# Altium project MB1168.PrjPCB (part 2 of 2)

## Sheet Peripherals.SchDoc: Peripherals
size A3; Project: STM32L073Z-EVAL; Date: Not used; ApprovedBy: Not used; CheckedBy: Not used; Author: Not used; CompanyName: STMicroelectronics; DrawnBy: Not used; Engineer: Not used; Organization: Not used; Address1: Not used; Address2: Not used; Address3: Not used; Address4: Not used; DocumentNumber: 5; Revision: Not used; SheetNumber: 6; SheetTotal: 13
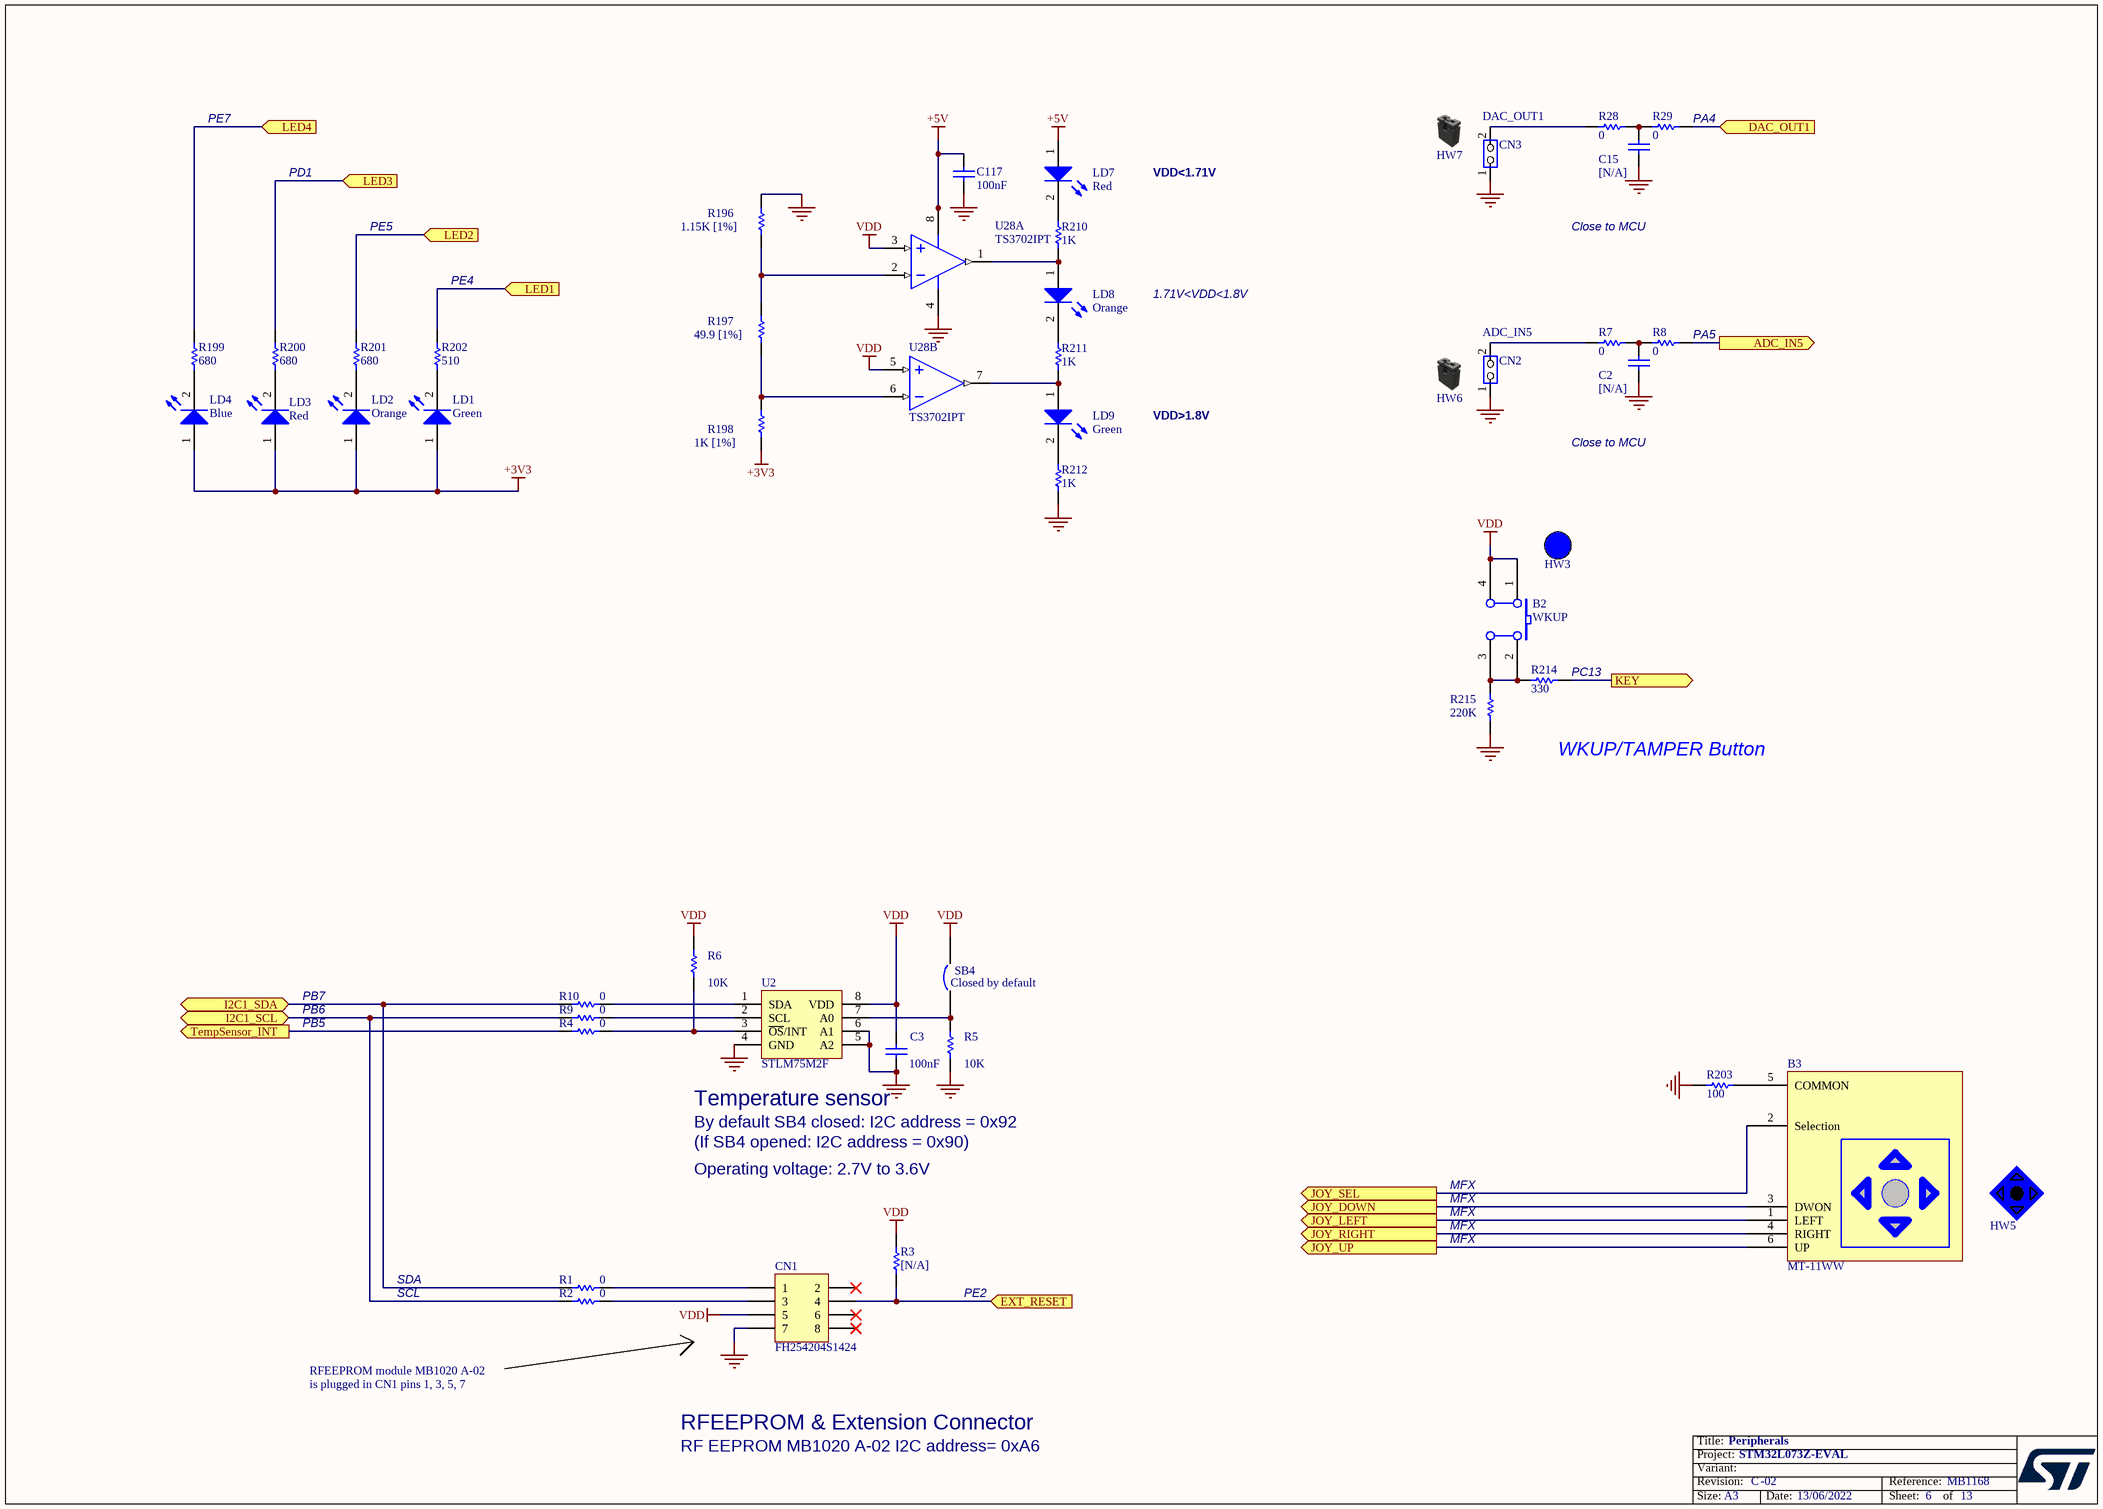
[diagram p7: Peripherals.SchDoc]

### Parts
B2  WKUP  [PB10]
B3  MT-11WW  [MT-008A]
C2  [N/A]  [0603C]
C3  100nF  [0402C]
C15  [N/A]  [0603C]
C117  100nF  [0402C]
CN1  FH254204S1424  [SSM-104-L-DH]
CN2  Silkscreen: ADC_IN5  [SIP2]  (hidden comment: Header 2X1)
CN3  Silkscreen: DAC_OUT1  [SIP2]  (hidden comment: Header 2X1)
HW3  BUTTON_HAT_BLUE  (value not drawn)  (mechanical)
HW5  JOYSTICK_BLUE_HAT  (value not drawn)  (mechanical)
HW6  Shunt Black 2.54mm  (value not drawn)  (mechanical)
HW7  Shunt Black 2.54mm  (value not drawn)  (mechanical)
LD1  Green  [0603D]
LD2  Orange  [0603D]
LD3  Red  [0603D]
LD4  Blue  [0603D]
LD7  Red  [0603D]
LD8  Orange  [0603D]
LD9  Green  [0603D]
R1  0  [0603R]
R2  0  [0603R]
R3  [N/A]  [0603R]
R4  0  [0603R]
R5  10K  [0402R]
R6  10K  [0402R]
R7  0  [0603R]
R8  0  [0603R]
R9  0  [0603R]
R10  0  [0603R]
R28  0  [0603R]
R29  0  [0603R]
R196  1.15K [1%]  [0603R]
R197  49.9 [1%]  [0603R]
R198  1K [1%]  [0603R]
R199  680  [0402R]
R200  680  [0402R]
R201  680  [0402R]
R202  510  [0402R]
R203  100  [0402R]
R210  1K  [0402R]
R211  1K  [0402R]
R212  1K  [0402R]
R214  330  [0603R]
R215  220K  [0402R]
SB4  Closed by default  [SB_0603]
U2  STLM75M2F  [SOIC8_1R27_4R9X6]
U28  TS3702IPT  [TSSOP8_0R65_3X6R4]  (parts A,B of 2)

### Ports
ADC_IN5 (out), DAC_OUT1 (in), EXT_RESET (in), I2C1_SCL (bidir), I2C1_SDA (bidir), JOY_DOWN (out), JOY_LEFT (out), JOY_RIGHT (out), JOY_SEL (out), JOY_UP (out), KEY (out), LED1 (in), LED2 (in), LED3 (in), LED4 (in), TempSensor_INT (out)

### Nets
+3V3: LD1.1(A) LD2.1(A) LD3.1(A) LD4.1(A) R198.1
+5V: C117.2 LD7.1(A) U28.8(V+)
GND: C2.1 C3.1 C15.1 C117.1 CN1.7 CN2.1(COMMON) CN3.1(COMMON) R5.2 R196.2 R203.1 R212.2 R215.2 U2.4(GND) U2.5(A2) U2.6(A1) U28.4(V-)
VDD: B2.1(A0) B2.4(A1) C3.2 CN1.5 R3.2 R6.1 SB4.2 U2.8(VDD) U28.3(IN+) U28.5(IN+)
PA5: R8.2 ; port ADC_IN5
PC13: R214.2 ; port KEY
PD1: R200.1 ; port LED3
PE4: R202.1 ; port LED1
PE5: R201.1 ; port LED2
PE7: R199.1 ; port LED4
NetB2_2: B2.2(B0) B2.3(B1) R214.1 R215.1
NetB3_1: B3.1(LEFT) ; port JOY_LEFT
NetB3_2: B3.2(Selection) ; port JOY_SEL
NetB3_3: B3.3(DWON) ; port JOY_DOWN
NetB3_4: B3.4(RIGHT) ; port JOY_RIGHT
NetB3_5: B3.5(COMMON) R203.2
NetB3_6: B3.6(UP) ; port JOY_UP
NetC2_2: C2.2 R7.2 R8.1
NetC15_2: C15.2 R28.2 R29.1
NetCN1_1: CN1.1 R1.2
NetCN1_3: CN1.3 R2.2
NetCN1_4: CN1.4 R3.1 ; port EXT_RESET
NetCN2_2: CN2.2(NO) R7.1
NetCN3_2: CN3.2(NO) R28.1
NetCN10_14: R4.2 ; port TempSensor_INT
NetJP2_1: R29.2 ; port DAC_OUT1
NetLD1_2: LD1.2(K) R202.2
NetLD2_2: LD2.2(K) R201.2
NetLD3_2: LD3.2(K) R200.2
NetLD4_2: LD4.2(K) R199.2
NetLD7_2: LD7.2(K) R210.1
NetLD8_1: LD8.1(A) R210.2 U28.1(OUT)
NetLD8_2: LD8.2(K) R211.1
NetLD9_1: LD9.1(A) R211.2 U28.7(OUT)
NetLD9_2: LD9.2(K) R212.1
NetR1_1: R1.1 R10.1 ; port I2C1_SDA
NetR2_1: R2.1 R9.1 ; port I2C1_SCL
NetR4_1: R4.1 R6.2 U2.3(~{OS}/INT)
NetR5_1: R5.1 SB4.1 U2.7(A0)
NetR9_2: R9.2 U2.2(SCL)
NetR10_2: R10.2 U2.1(SDA)
NetR196_1: R196.1 R197.2 U28.2(IN-)
NetR197_1: R197.1 R198.2 U28.6(IN-)

Not connected (* = marked no-connect by the designer): CN1 2* 6* 8*

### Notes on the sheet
- PE7
- PD1
- VDD<1.71V
- (near R29) PA4
- PE5
- Close to MCU
- PE4
- 1.71V<VDD<1.8V
- (near R8) PA5
- VDD>1.8V
- (near R214) PC13
- WKUP/TAMPER Button
- PB7
- PB6
- PB5
- Temperature sensor
- By default SB4 closed: I2C address = 0x92
- Operating voltage: 2.7V to 3.6V
- (If SB4 opened: I2C address = 0x90)
- MFX
- SDA
- SCL
- PE2
- RFEEPROM module MB1020 A-02
  is plugged in CN1 pins 1, 3, 5, 7
- RF EEPROM MB1020 A-02 I2C address= 0xA6
- RFEEPROM & Extension Connector

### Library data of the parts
B2 = SW PUSHBUTTON: SE PUSHBUTTON; Ordered by: Subcon; Assembly: Blue; Silkscreen: Wkup/Tamper
B3 = MT-008A: Joystick; Ordered by: Subcon; Assembly: with button
C2 C15 = cap: Capacitor; Value: 100pF; Ordered by: Subcon; Fitted: NO
C3 = cap: Capacitor; Value: 100pF; Ordered by: Subcon
C117 = CAP: Capacitor; Value: 100pF; Ordered by: Subcon
CN1 = SSM-104-L-DH: Header, 5-Pin, Dual row; Manuf_1: towneS; Ordered by: Subcon; Silkscreen: RF_EEPROM; Assembly: with ANT7-M24LR-A (MB1020-A02)
CN2 CN3 = JP2: Manuf_1: LWCONN; Manuf_Part_1: 313102S111116; Ordered by: Subcon
LD1-LD4 LD8 = LED2: Typical RED, GREEN, YELLOW, AMBER GaAs LED; Ordered by: Subcon
LD7 = LED2: Typical RED, GREEN, YELLOW, AMBER GaAs LED; Ordered by: Subcon; Silkscreen: VDD<1.7V
LD9 = LED2: Typical RED, GREEN, YELLOW, AMBER GaAs LED; Ordered by: Subcon; Silkscreen: VDD>1.8V
R1 R2 R4 R7-R10 R28 R29 R196 R197 R199-R203 R214 = Res1: Resistor; Value: 1K; Ordered by: Subcon
R3 = Res1: Resistor; Value: 1K; Ordered by: Subcon; Fitted: NO
R5 R6 R215 = res1: Resistor; Value: 1K; Ordered by: Subcon
R198 R210-R212 = Res1: Resistor; Ordered by: Subcon
SB4 = Circuit Breaker: Ordered by: Subcon; Comments: Solder bridge
U2 = STLM75DW2F: Ordered by: ST; ECCN_US/EU: EAR99/NEC; Ref St: 9177005
U28 = LM393PT: Ordered by: ST; ECCN_US/EU: EAR99/NEC; Ref St: 9177424

## Sheet Power.SchDoc: Power
size A3; Project: STM32L073Z-EVAL; Date: Not used; ApprovedBy: Not used; CheckedBy: Not used; Author: Not used; CompanyName: STMicroelectronics; DrawnBy: Not used; Engineer: Not used; Organization: Not used; Address1: Not used; Address2: Not used; Address3: Not used; Address4: Not used; DocumentNumber: 4; Revision: Not used; SheetNumber: 5; SheetTotal: 13
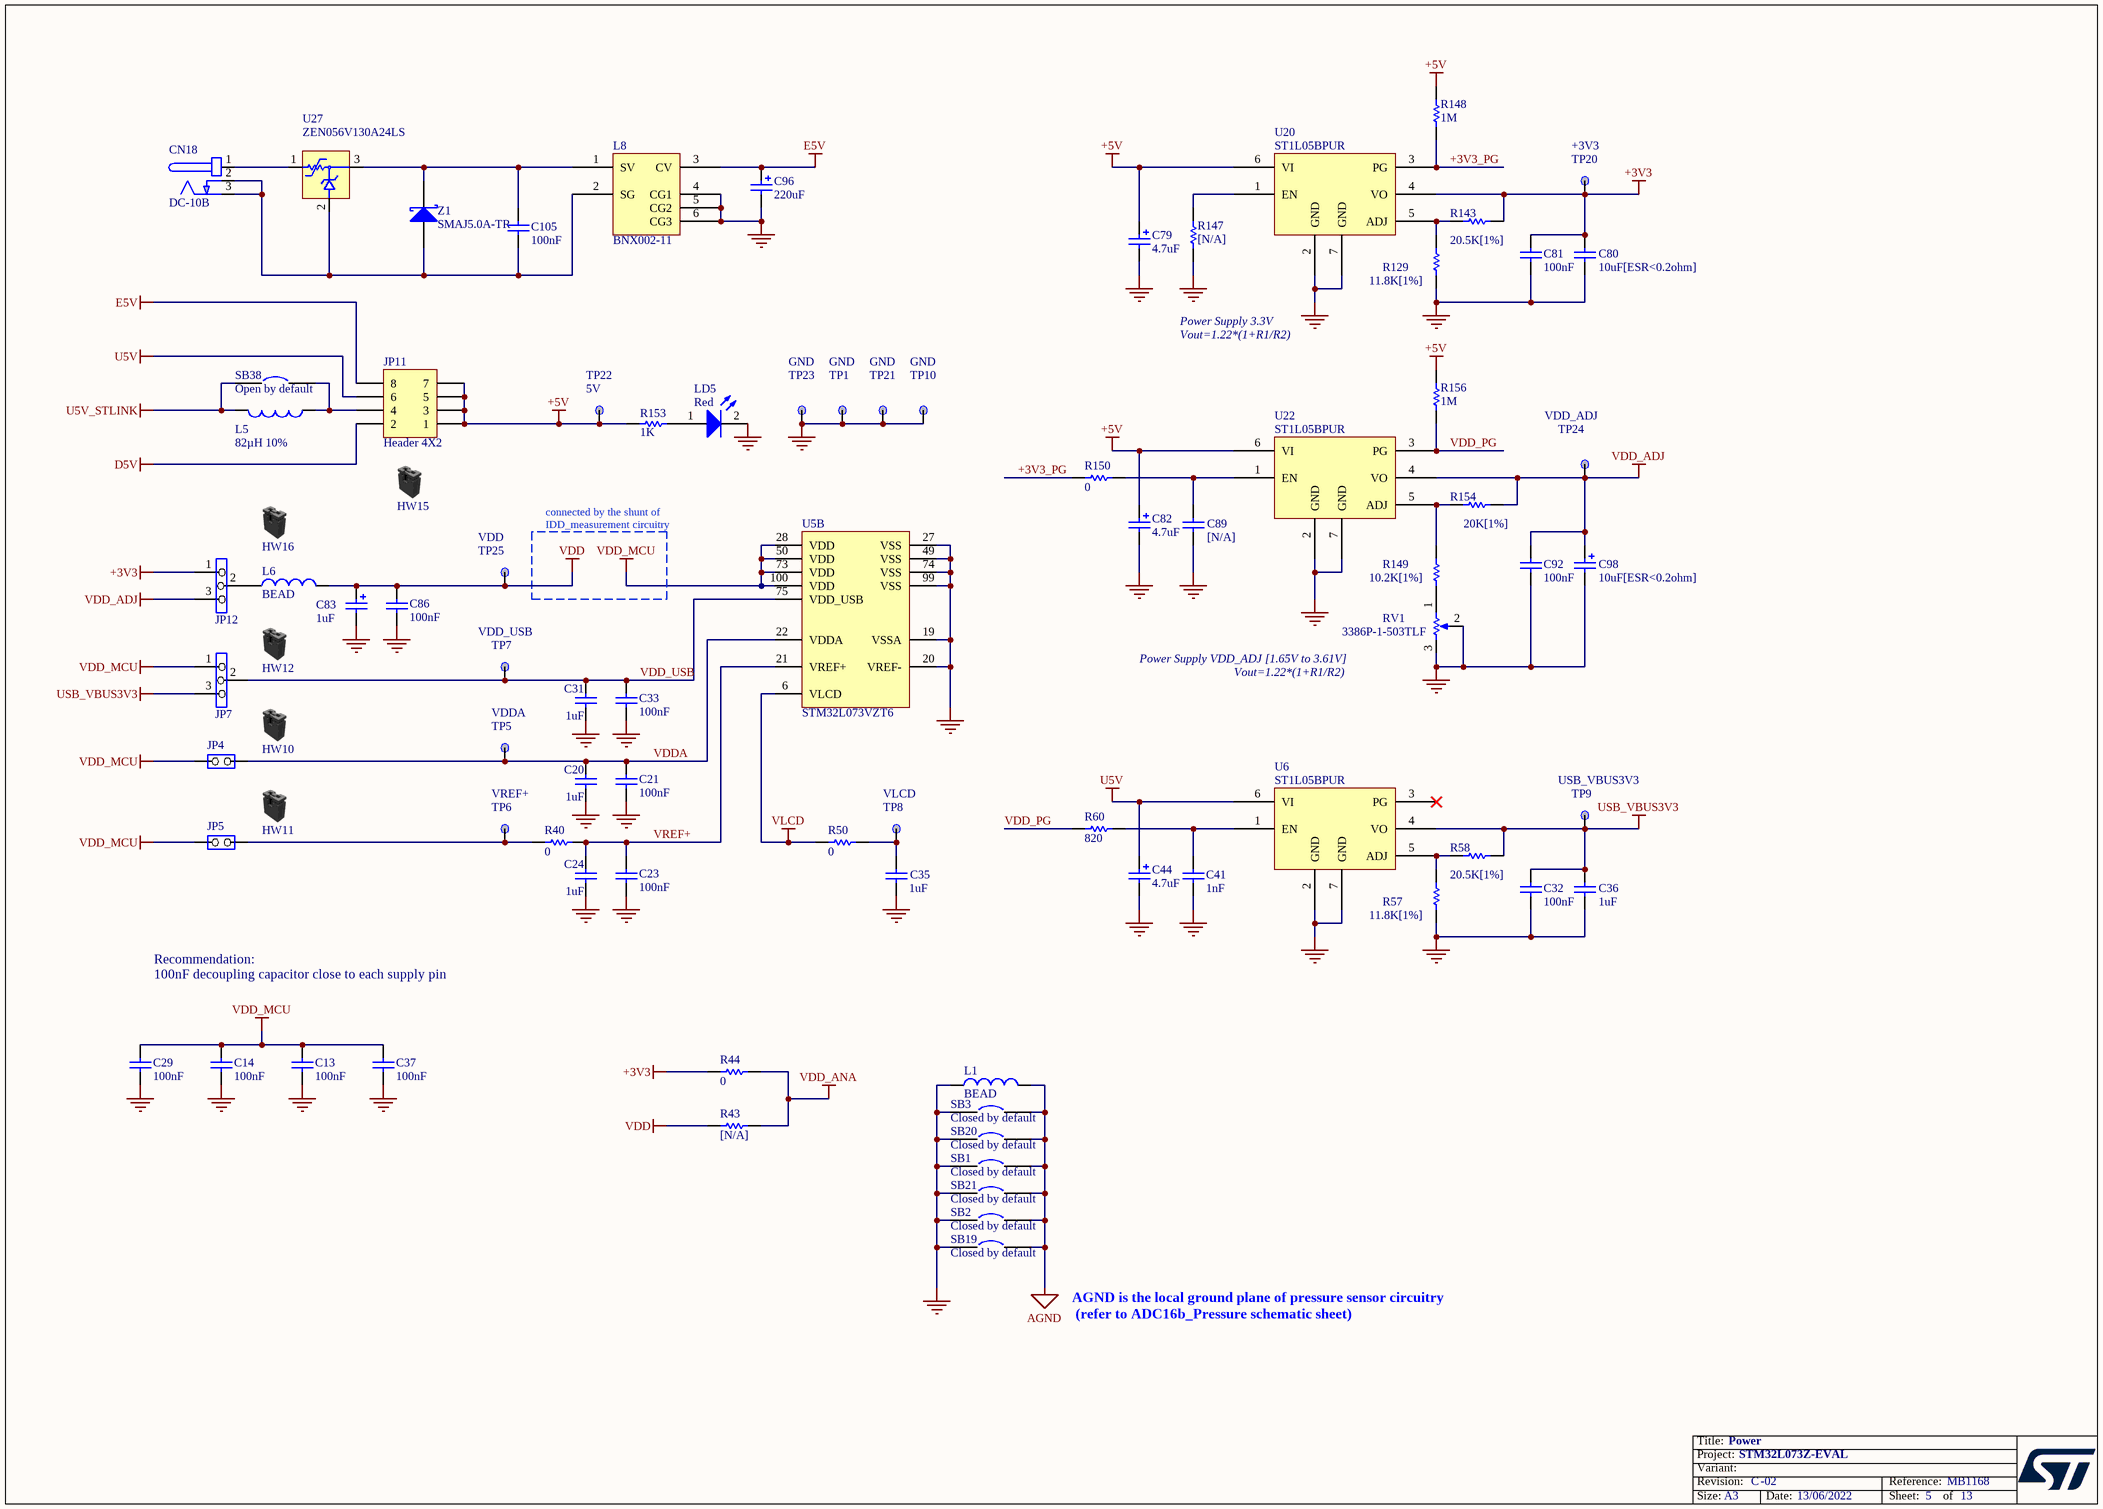
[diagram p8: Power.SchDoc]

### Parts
C13  100nF  [0402C]
C14  100nF  [0402C]
C20  1uF  [0603C]
C21  100nF  [0402C]
C23  100nF  [0402C]
C24  1uF  [0603C]
C29  100nF  [0402C]
C31  1uF  [0603C]
C32  100nF  [0402C]
C33  100nF  [0402C]
C35  1uF  [0603C]
C36  1uF  [0603C]
C37  100nF  [0402C]
C41  1nF  [0603C]
C44  4.7uF  [TAN-A]
C79  4.7uF  [TAN-A]
C80  10uF[ESR<0.2ohm]  [0805C]
C81  100nF  [0402C]
C82  4.7uF  [TAN-A]
C83  1uF  [TAN-A]
C86  100nF  [0402C]
C89  [N/A]  [0603C]
C92  100nF  [0402C]
C96  220uF  [c310m-6]
C98  10uF[ESR<0.2ohm]  [0805C]
C105  100nF  [0402C]
CN18  DC-10B  [PWR_JACK_DC10]
HW10  Shunt Black 2.54mm  (value not drawn)  (mechanical)
HW11  Shunt Black 2.54mm  (value not drawn)  (mechanical)
HW12  Shunt Black 2.54mm  (value not drawn)  (mechanical)
HW15  Shunt Black 2.54mm  (value not drawn)  (mechanical)
HW16  Shunt Black 2.54mm  (value not drawn)  (mechanical)
JP4  (no value)  [SIP2]
JP5  (no value)  [SIP2]
JP7  (no value)  [SIP3]
JP11  Header 4X2  [HDR_2X4_2R54]
JP12  (no value)  [SIP3]
L1  BEAD  [0603L]
L5  82µH 10%  [LSM2_4R9X4R9_H4R1]
L6  BEAD  [0603L]
L8  BNX002-11  [BNX001]
LD5  Red  [0603D]
R40  0  [0603R]
R43  [N/A]  [0603R]
R44  0  [0603R]
R50  0  [0603R]
R57  11.8K[1%]  [0603R]
R58  20.5K[1%]  [0603R]
R60  820  [0603R]
R129  11.8K[1%]  [0603R]
R143  20.5K[1%]  [0603R]
R147  [N/A]  [0603R]
R148  1M  [0603R]
R149  10.2K[1%]  [0603R]
R150  0  [0603R]
R153  1K  [0402R]
R154  20K[1%]  [0603R]
R156  1M  [0603R]
RV1  3386P-1-503TLF  [3386P]
SB1  Closed by default  [SB_0603]
SB2  Closed by default  [SB_0603]
SB3  Closed by default  [SB_0603]
SB19  Closed by default  [SB_0603]
SB20  Closed by default  [SB_0603]
SB21  Closed by default  [SB_0603]
SB38  Open by default  [SB_0603]
TP1  Silkscreen: GND  [TP]  (hidden comment: TP)
TP5  Silkscreen: VDDA  [TP]  (hidden comment: TP)
TP6  Silkscreen: VREF+  [TP]  (hidden comment: TP)
TP7  Silkscreen: VDD_USB  [TP]  (hidden comment: TP)
TP8  Silkscreen: VLCD  [TP]  (hidden comment: TP)
TP9  Silkscreen: USB_VBUS3V3  [TP]  (hidden comment: TP)
TP10  Silkscreen: GND  [TP]  (hidden comment: TP)
TP20  Silkscreen: +3V3  [TP]  (hidden comment: TP)
TP21  Silkscreen: GND  [TP]  (hidden comment: TP)
TP22  Silkscreen: 5V  [TP]  (hidden comment: TP)
TP23  Silkscreen: GND  [TP]  (hidden comment: TP)
TP24  Silkscreen: VDD_ADJ  [TP]  (hidden comment: TP)
TP25  Silkscreen: VDD  [TP]  (hidden comment: TP)
U5  STM32L073VZT6  [IC149_100_025_B5]  (part B of 2)
U6  ST1L05BPUR  [DFN6_0R95_3X3]
U20  ST1L05BPUR  [DFN6_0R95_3X3]
U22  ST1L05BPUR  [DFN6_0R95_3X3]
U27  ZEN056V130A24LS  [TYCO_ZEN056V130A24LS]
Z1  SMAJ5.0A-TR  [sma]

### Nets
+3V3: C80.1 C81.1 JP12.1 R44.1 R143.1 TP20.1 U20.4(VO)
+5V: C79.1 C82.1 JP11.1 JP11.3 JP11.5 JP11.7 R148.1 R153.2 R156.1 TP22.1 U20.6(VI) U22.6(VI)
AGND: L1.2 SB1.2 SB2.2 SB3.2 SB19.2 SB20.2 SB21.2
D5V: JP11.2
E5V: C96.1 JP11.8 L8.3(CV)
GND: C13.1 C14.1 C20.2 C21.1 C23.1 C24.2 C29.1 C31.2 C32.2 C33.1 C35.1 C36.2 C37.1 C41.2 C44.2 C79.2 C80.2 C81.2 C82.2 C83.2 C86.1 C89.1 C92.2 C96.2 C98.2 L1.1 L8.4(CG1) L8.5(CG2) L8.6(CG3) LD5.2(K) R57.2 R129.2 R147.2 RV1.2(TAP) RV1.3(TOP) SB1.1 SB2.1 SB3.1 SB19.1 SB20.1 SB21.1 TP1.1 TP10.1 TP21.1 TP23.1 U5.19(VSSA) U5.20(VREF-) U5.27(VSS) U5.49(VSS) U5.74(VSS) U5.99(VSS) U6.2(GND) U6.7(GND) U20.2(GND) U20.7(GND) U22.2(GND) U22.7(GND)
U5V: C44.1 JP11.6 U6.6(VI)
U5V_STLINK: L5.2 SB38.1
USB_VBUS3V3: C32.1 C36.1 JP7.3 R58.1 TP9.1 U6.4(VO)
VDD: C83.1 C86.2 L6.2 R43.1 TP25.1
VDD_ADJ: C92.1 C98.1 JP12.3 R154.1 TP24.1 U22.4(VO)
VDD_ANA: R43.2 R44.2
VDD_MCU: C13.2 C14.2 C29.2 C37.2 JP4.1(COMMON) JP5.1(COMMON) JP7.1 U5.28(VDD) U5.50(VDD) U5.73(VDD) U5.100(VDD)
VLCD: R50.1 U5.6(VLCD)
+3V3_PG: R148.2 R150.1 U20.3(PG)
VDD_PG: R60.1 R156.2 U22.3(PG)
VDD_USB: C31.1 C33.2 JP7.2 TP7.1 U5.75(VDD_USB)
VDDA: C20.1 C21.2 JP4.2(NO) TP5.1 U5.22(VDDA)
VREF+: C23.2 C24.1 R40.2 U5.21(VREF+)
NetC35_2: C35.2 R50.2 TP8.1
NetC41_1: C41.1 R60.2 U6.1(EN)
NetC89_2: C89.2 R150.2 U22.1(EN)
NetC105_1: C105.1 L8.1(SV) U27.3 Z1.2(K)
NetC105_2: C105.2 CN18.2(GND) CN18.3(GND) L8.2(SG) U27.2 Z1.1(A)
NetCN18_1: CN18.1(+) U27.1
NetJP5_2: JP5.2(NO) R40.1 TP6.1
NetJP11_4: JP11.4 L5.1 SB38.2
NetJP12_2: JP12.2 L6.1
NetLD5_1: LD5.1(A) R153.1
NetR57_1: R57.1 R58.2 U6.5(ADJ)
NetR129_1: R129.1 R143.2 U20.5(ADJ)
NetR147_1: R147.1 U20.1(EN)
NetR149_1: R149.1 R154.2 U22.5(ADJ)
NetR149_2: R149.2 RV1.1(BOT)

Not connected (* = marked no-connect by the designer): U6 3(PG)*

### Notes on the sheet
- Power Supply 3.3V
- Vout=1.22*(1+R1/R2)
- (near TP25) connected by the shunt of
  IDD_measurement circuitry
- Power Supply VDD_ADJ [1.65V to 3.61V]
- Recommendation:
  100nF decoupling capacitor close to each supply pin
- AGND is the local ground plane of pressure sensor circuitry
  (refer to ADC16b_Pressure schematic sheet)

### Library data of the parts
C13 C14 C29 C37 = CAP: Capacitor; Ordered by: Subcon
C20 C24 C31 C35 = CAP: Capacitor; Value: 100nF; Ordered by: Subcon
C21 C23 C32 C33 C36 C41 C81 C86 C92 = Cap: Capacitor; Value: 10nF; Ordered by: Subcon
C44 = Cap Pol1: Polarized Capacitor (Radial); Value: 100pF; Ordered by: Subcon
C79 C82 C96 = Cap Pol1: Polarized Capacitor (Radial); Ordered by: Subcon
C80 = Cap: Capacitor; Value: 10uF; Ordered by: Subcon
C83 = Cap Pol1: Polarized Capacitor; Ordered by: Subcon
C89 = cap: as C2 on sheet Peripherals
C98 = Cap Pol1: Polarized Capacitor (Radial); Value: 10uF; Ordered by: Subcon
C105 = CAP: as C117 on sheet Peripherals
CN18 = PJ202A: Manuf_1: wealthmetal; Manuf_Part_1: DC-005-2.5; Ordered by: Subcon; Comments: power jack; Silkscreen: PSU_E5V
JP4 = JP2: Ordered by: Subcon; Silkscreen: VDDA; Assembly: closed
JP5 = JP2: Ordered by: Subcon; Silkscreen: VREF+; Assembly: closed
JP7 = Jumper3: Ordered by: Subcon; Silkscreen: 1,2: VDD_MCU / 2,3: VBUS; Assembly: 1-2 closed (MCU)
JP11 = Header 4X2: Header, 4-Pin, Dual row; Ordered by: Subcon; Silkscreen: 7,8: E5V /5,6: U5V / 3,4: STlk / 1,2: D5V; Assembly: 7-8 (E5V)
JP12 = Jumper3: Ordered by: Subcon; Silkscreen: 1,2: +3V3 / 2,3: VDD_ADJ; Assembly: 1-2 (+3V3)
L1 L6 = Inductor: Bead,600R,350mA,0603; Manuf_1: Tai-tech; Manuf_Part_1: FCM1608KF-601T05; Manuf_2: Wurth Elektronik; Manuf_Part_2: 742863160; Value: 100uH; Ordered by: Subcon
L5 = Ind_82µH_0.65A_10%: Power Inductor 82µH 0,65A; Manuf_Part_1: PSI054T-820MS-11; Manuf_1: CYNTEC; Manuf_Part_2: A916CY-820M; Manuf_2: TOKO; Order_2: 752-1406; Ordered by: Subcon
L8 = BNX002: Manuf_1: MURATA; Ordered by: Subcon
LD5 = LED2: Typical RED, GREEN, YELLOW, AMBER GaAs LED; Ordered by: Subcon; Silkscreen: +5V
R40 R44 R50 R57 R58 R129 R143 R149 R154 = Res1: Resistor; Value: 1K; Ordered by: Subcon
R43 R147 = res1: Resistor; Value: 1K; Ordered by: Subcon; Fitted: NO
R60 R148 R150 R156 = res1: Resistor; Value: 1K; Ordered by: Subcon
R153 = res1: Resistor; Ordered by: Subcon
RV1 = RV: Potentiometer 50K; Ordered by: Subcon; Comments: 50K potentiometer; Silkscreen: VDD_ADJ
SB1-SB3 SB19-SB21 = Circuit Breaker: as SB4 on sheet Peripherals
SB38 = Circuit Breaker: Ordered by: Subcon; Comments: Solder bridge; Fitted: NO
TP1 TP5-TP10 TP20-TP25 = TP: Ordered by: Subcon; Fitted: NO
U5 = BigNemo: Manuf_Part_1: FG=32L073VZT6$x3 cut 2.0 marking "B"; Ordered by: ST; ECCN_US/EU: 3A991A2/NEC; Ref St: 9175165
U6 U20 U22 = ST1L05: Ordered by: ST; ECCN_US/EU: EAR99/NEC; Ref St: 9176239
U27 = ZEN056V130A24LS: Ordered by: Subcon; ECCN_US/EU: EAR99/NEC
Z1 = D Schottky: Schottky Diode; Code - JEDEC: DO-214-AA; Ordered by: Subcon; ECCN_US/EU: EAR99/NEC

## Sheet STLINK.SchDoc: STLINK
size A3; Project: STM32L073Z-EVAL; Date: Not used; ApprovedBy: Not used; CheckedBy: Not used; Author: Not used; CompanyName: STMicroelectronics; DrawnBy: Not used; Engineer: Not used; Organization: Not used; Address1: Not used; Address2: Not used; Address3: Not used; Address4: Not used; DocumentNumber: 12; Revision: Not used; SheetNumber: 13; SheetTotal: 13
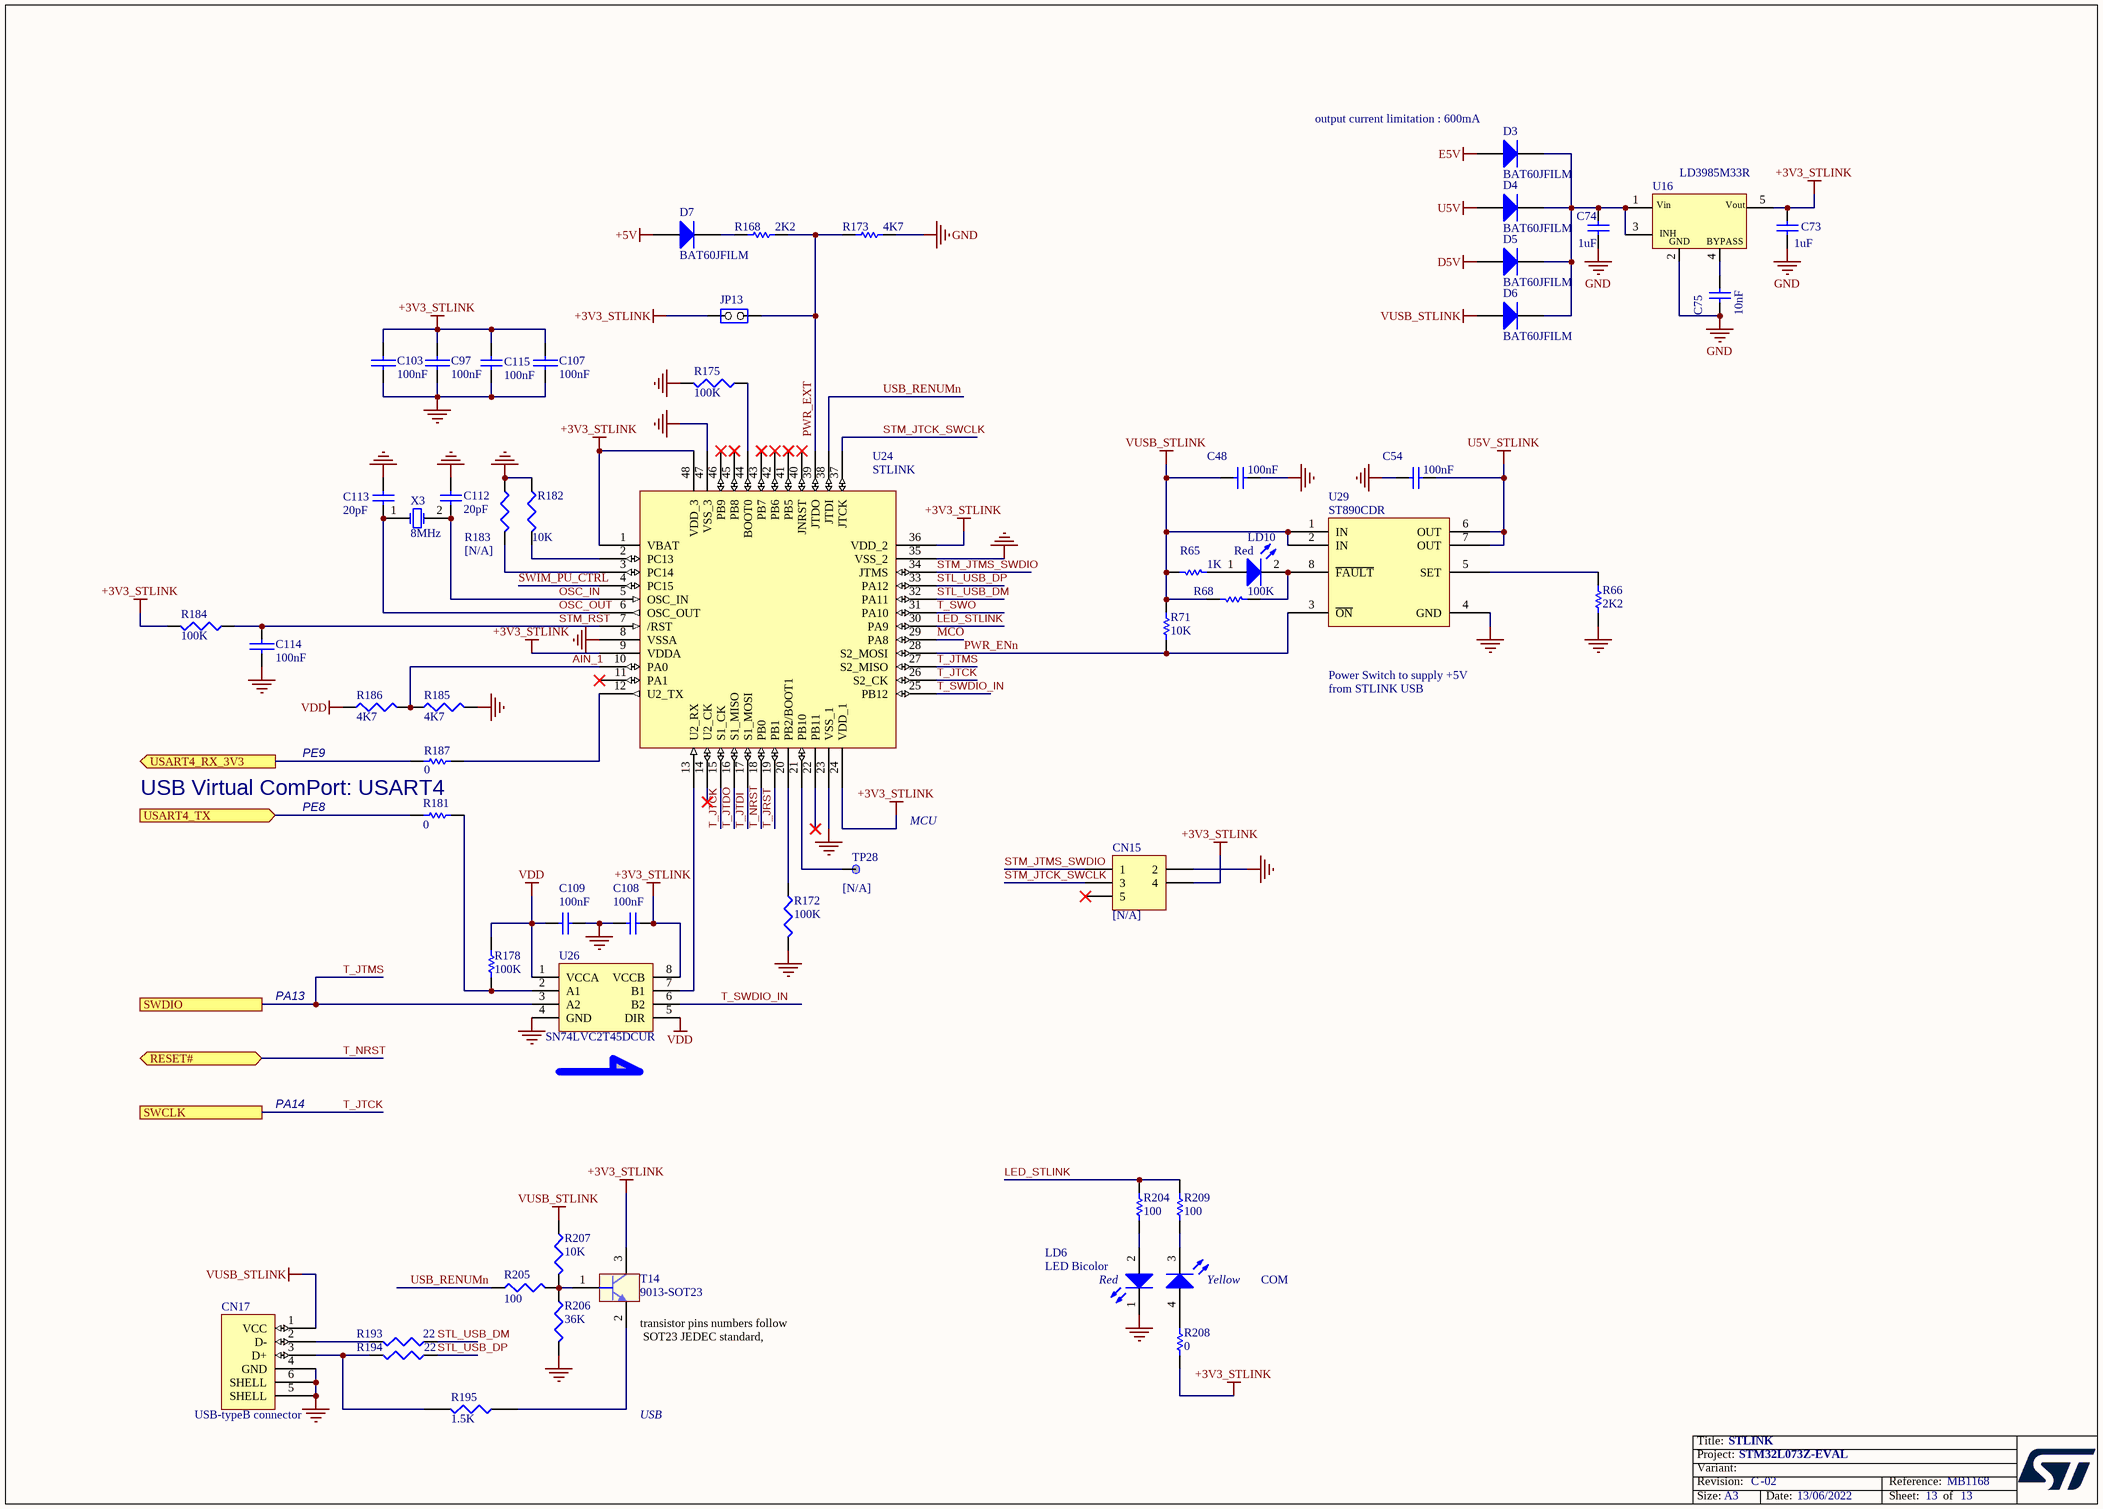
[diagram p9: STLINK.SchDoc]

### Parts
C48  100nF  [0402C]
C54  100nF  [0402C]
C73  1uF  [0603C]
C74  1uF  [0603C]
C75  10nF  [0402C]
C97  100nF  [0402C]
C103  100nF  [0402C]
C107  100nF  [0402C]
C108  100nF  [0402C]
C109  100nF  [0402C]
C112  20pF  [0402C]
C113  20pF  [0402C]
C114  100nF  [0402C]
C115  100nF  [0402C]
CN15  [N/A]  [HDR_2X3-1_2R54-6]
CN17  USB-typeB connector  [USB-B]
D3  BAT60JFILM  [SOD-323]
D4  BAT60JFILM  [SOD-323]
D5  BAT60JFILM  [SOD-323]
D6  BAT60JFILM  [SOD-323]
D7  BAT60JFILM  [SOD-323]
JP13  (no value)  [SIP2]
LD6  LED Bicolor  Silkscreen: COM  [LED2_3528]
LD10  Red  [0603D]
R65  1K  [0402R]
R66  2K2  [0402R]
R68  100K  [0402R]
R71  10K  [0402R]
R168  2K2  [0402R]
R172  100K  [0402R]
R173  4K7  [0402R]
R175  100K  [0402R]
R178  100K  [0402R]
R181  0  [0603R]
R182  10K  [0402R]
R183  [N/A]  [0603R]
R184  100K  [0402R]
R185  4K7  [0402R]
R186  4K7  [0402R]
R187  0  [0603R]
R193  22  [0402R]
R194  22  [0402R]
R195  1.5K  [0402R]
R204  100  [0402R]
R205  100  [0402R]
R206  36K  [0402R]
R207  10K  [0402R]
R208  0  [0603R]
R209  100  [0402R]
T14  9013-SOT23  [SOT-23]
TP28  [N/A]  [TP]
U16  LD3985M33R  [SOT23-5]
U24  STLINK  [LQFP48_0R5_9X9]
U26  SN74LVC2T45DCUR  [USOP8_0R5_2X3R1]
U29  ST890CDR  [SOIC8_1R27_4R9X6]
X3  8MHz  [XTAL_2SM_12R7X4R7]

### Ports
RESET# (bidir), SWCLK, SWDIO, USART4_RX_3V3 (out), USART4_TX (in)

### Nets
+3V3_STLINK: C73.1 C97.2 C103.2 C107.2 C108.1 C115.1 CN15.4 JP13.1(COMMON) R184.2 R208.2 T14.3(C) U16.5(Vout) U24.1(VBAT) U24.9(VDDA) U24.24(VDD_1) U24.36(VDD_2) U24.48(VDD_3) U26.8(VCCB)
+5V: D7.1(A)
D5V: D5.1(A)
E5V: D3.1(A)
GND: C48.2 C54.1 C73.2 C74.2 C75.2 C97.1 C103.1 C107.1 C108.2 C109.2 C112.1 C113.1 C114.1 C115.2 CN15.2 CN17.4(GND) CN17.5(SHELL) CN17.6(SHELL) LD6.1(RED_cathode) R66.2 R172.2 R173.1 R175.2 R182.1 R183.1 R185.2 R206.2 U16.2(GND) U24.8(VSSA) U24.23(VSS_1) U24.35(VSS_2) U24.47(VSS_3) U26.4(GND) U29.4(GND)
U5V: D4.1(A)
U5V_STLINK: C54.2 U29.6(OUT) U29.7(OUT)
VDD: C109.1 R178.1 R186.1 U26.1(VCCA) U26.5(DIR)
VUSB_STLINK: C48.1 CN17.1(VCC) D6.1(A) R65.1 R68.1 R71.2 R207.1 U29.1(IN) U29.2(IN)
AIN_1: R185.1 R186.2 U24.10(PA0)
LED_STLINK: R204.1 R209.1 U24.30(PA9)
MCO: U24.29(PA8)
OSC_IN: C112.2 U24.5(OSC_IN) X3.2(OSC2)
OSC_OUT: C113.2 U24.6(OSC_OUT) X3.1(OSC1)
PE8: R181.1 ; port USART4_TX
PE9: R187.2 ; port USART4_RX_3V3
PWR_ENn: R71.1 U24.28(S2_MOSI) U29.3(~{ON})
PWR_EXT: JP13.2(NO) R168.1 R173.2 U24.39(JTDO)
STL_USB_DM: R193.1 U24.32(PA11)
STL_USB_DP: R194.1 U24.33(PA12)
STM_JTCK_SWCLK: CN15.3 U24.37(JTCK)
STM_JTMS_SWDIO: CN15.1 U24.34(JTMS)
STM_RST: C114.2 R184.1 U24.7(/RST)
SWIM_PU_CTRL: U24.4(PC15)
T_JRST: U24.19(PB1)
T_JTCK: U24.15(S1_CK) U24.26(S2_CK) ; port SWCLK
T_JTDI: U24.17(S1_MOSI)
T_JTDO: U24.16(S1_MISO)
T_JTMS: U24.27(S2_MISO) U26.3(A2) ; port SWDIO
T_NRST: U24.18(PB0) ; port RESET#  [project net RESET#]
T_SWDIO_IN: U24.25(PB12) U26.6(B2)
T_SWO: U24.31(PA10)
USB_RENUMn: R205.1 U24.38(JTDI)
NetC74_1: C74.1 D3.2(K) D4.2(K) D5.2(K) D6.2(K) U16.1(Vin) U16.3(CE)
NetC75_1: C75.1 U16.4(BYPASS)
NetCN17_2: CN17.2(D-) R193.2
NetCN17_3: CN17.3(D+) R194.2 R195.2
NetD7_2: D7.2(K) R168.2
NetLD6_2: LD6.2(Red_anode) R204.2
NetLD6_3: LD6.3(YellowGreen_cathode) R209.2
NetLD6_4: LD6.4(YellowGreen_anode) R208.1
NetLD10_1: LD10.1(A) R65.2
NetLD10_2: LD10.2(K) R68.2 U29.8(~{FAULT})
NetR66_1: R66.1 U29.5(SET)
NetR172_1: R172.1 U24.20(PB2/BOOT1)
NetR175_1: R175.1 U24.44(BOOT0)
NetR178_2: R178.2 R181.2 U26.2(A1)
NetR182_2: R182.2 U24.2(PC13)
NetR183_2: R183.2 U24.3(PC14)
NetR187_1: R187.1 U24.12(U2_TX)
NetR195_1: R195.1 T14.2(E)
NetR205_2: R205.2 R206.1 R207.2 T14.1(B)
NetTP28_1: TP28.1 U24.21(PB10)
NetU24_13: U24.13(U2_RX) U26.7(B1)

Not connected (* = marked no-connect by the designer): CN15 5*; U24 11(PA1)* 14(U2_CK)* 22(PB11)* 40(JNRST)* 41(PB5)* 42(PB6)* 43(PB7)* 45(PB8)* 46(PB9)*

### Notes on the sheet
- (near D3) output current limitation : 600mA
- Power Switch to supply +5V from STLINK USB
- PE9
- USB Virtual ComPort: USART4
- PE8
- MCU
- PA13
- PA14
- (near T14) transistor pins numbers follow
  SOT23 JEDEC standard,
- USB

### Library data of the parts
C48 C54 = Capacitor_ST: Capacitor 0402 / 0603 / 0805; Ordered by: Subcon
C73 C74 = CAP: as C20 on sheet Power
C75 = Cap: Capacitor; Ordered by: Subcon
C97 C103 C107 C114 = CAP: Ordered by: Subcon
C108 C109 C112 C113 = CAP: as C117 on sheet Peripherals
C115 = Cap: as C21 on sheet Power
CN15 = Header 3X2: Header, 3-Pin, Dual row; Ordered by: Subcon; Fitted: NO
CN17 = USB-typeB connector: Manuf_1: txgagroup; Manuf_Part_1: 4414BF20BO; Ordered by: Subcon; Silkscreen: ST-LINK/V2
D3-D7 = Diode: Default Diode; Code - JEDEC: DO-214-AB; Ordered by: ST; ECCN_US/EU: EAR99/NEC; Ref St: 9151097
JP13 = JP2: Ordered by: Subcon; Silkscreen: Pwr_ext; Assembly: opened
LD6 = HSMF-A201-A00J1: Ordered by: Subcon
LD10 = LED2: as LD1 on sheet Peripherals
R65 = Res1: Resistor; Ordered by: Subcon
R66 R168 R173 = res1: Resistor; Value: 1K; Ordered by: Subcon
R68 R178 R181 R187 R204 R208 R209 = Res1: Resistor; Value: 1K; Ordered by: Subcon
R71 = Resistor_ST: Resistor; Ordered by: Subcon
R172 R175 R184 R193 R194 = RES1: Resistor; Ordered by: Subcon
R182 R205-R207 = R: Resistor; Right: 20; Bottom: 30; Ordered by: Subcon
R183 = R: Right: 20; Bottom: 30; Ordered by: Subcon; Fitted: NO
R185 R186 R195 = RES1: Ordered by: Subcon
T14 = 9013-SOT23: NPN Bipolar Transistor; Manuf_Part_1: MMBT2222ALT1G; Ordered by: Subcon; ECCN_US/EU: EAR99/NEC
TP28 = TP: Ordered by: Subcon; Fitted: NO
U16 = LD3985M33R: Ultra low drop-low noise BiCMOS voltage, regulators low ESR capacitors compatible; Manuf_1: ST; Ref St: 9176161; ECCN_US/EU: EAR99/NEC
U24 = STM32F10x(48pin): Manuf_Part_1: STM32F103CBT6; Ordered by: ST; ECCN_US/EU: 3A991A2/NEC; Ref St: 9175111
U26 = SN74LVC2T45DCUT: Ordered by: Subcon; ECCN_US/EU: EAR99/NEC
U29 = ST890CDR: Ordered by: ST; ECCN_US/EU: EAR99/NEC; Ref St: 9172002
X3 = XTAL: Crystal Oscillator; Ordered by: Subcon

## Sheet TFT_MicroSD.SchDoc: TFT_MicroSD
size A3; Project: STM32L073Z-EVAL; Date: Not used; ApprovedBy: Not used; CheckedBy: Not used; Author: Not used; CompanyName: STMicroelectronics; DrawnBy: Not used; Engineer: Not used; Organization: Not used; Address1: Not used; Address2: Not used; Address3: Not used; Address4: Not used; DocumentNumber: 6; Revision: Not used; SheetNumber: 7; SheetTotal: 13
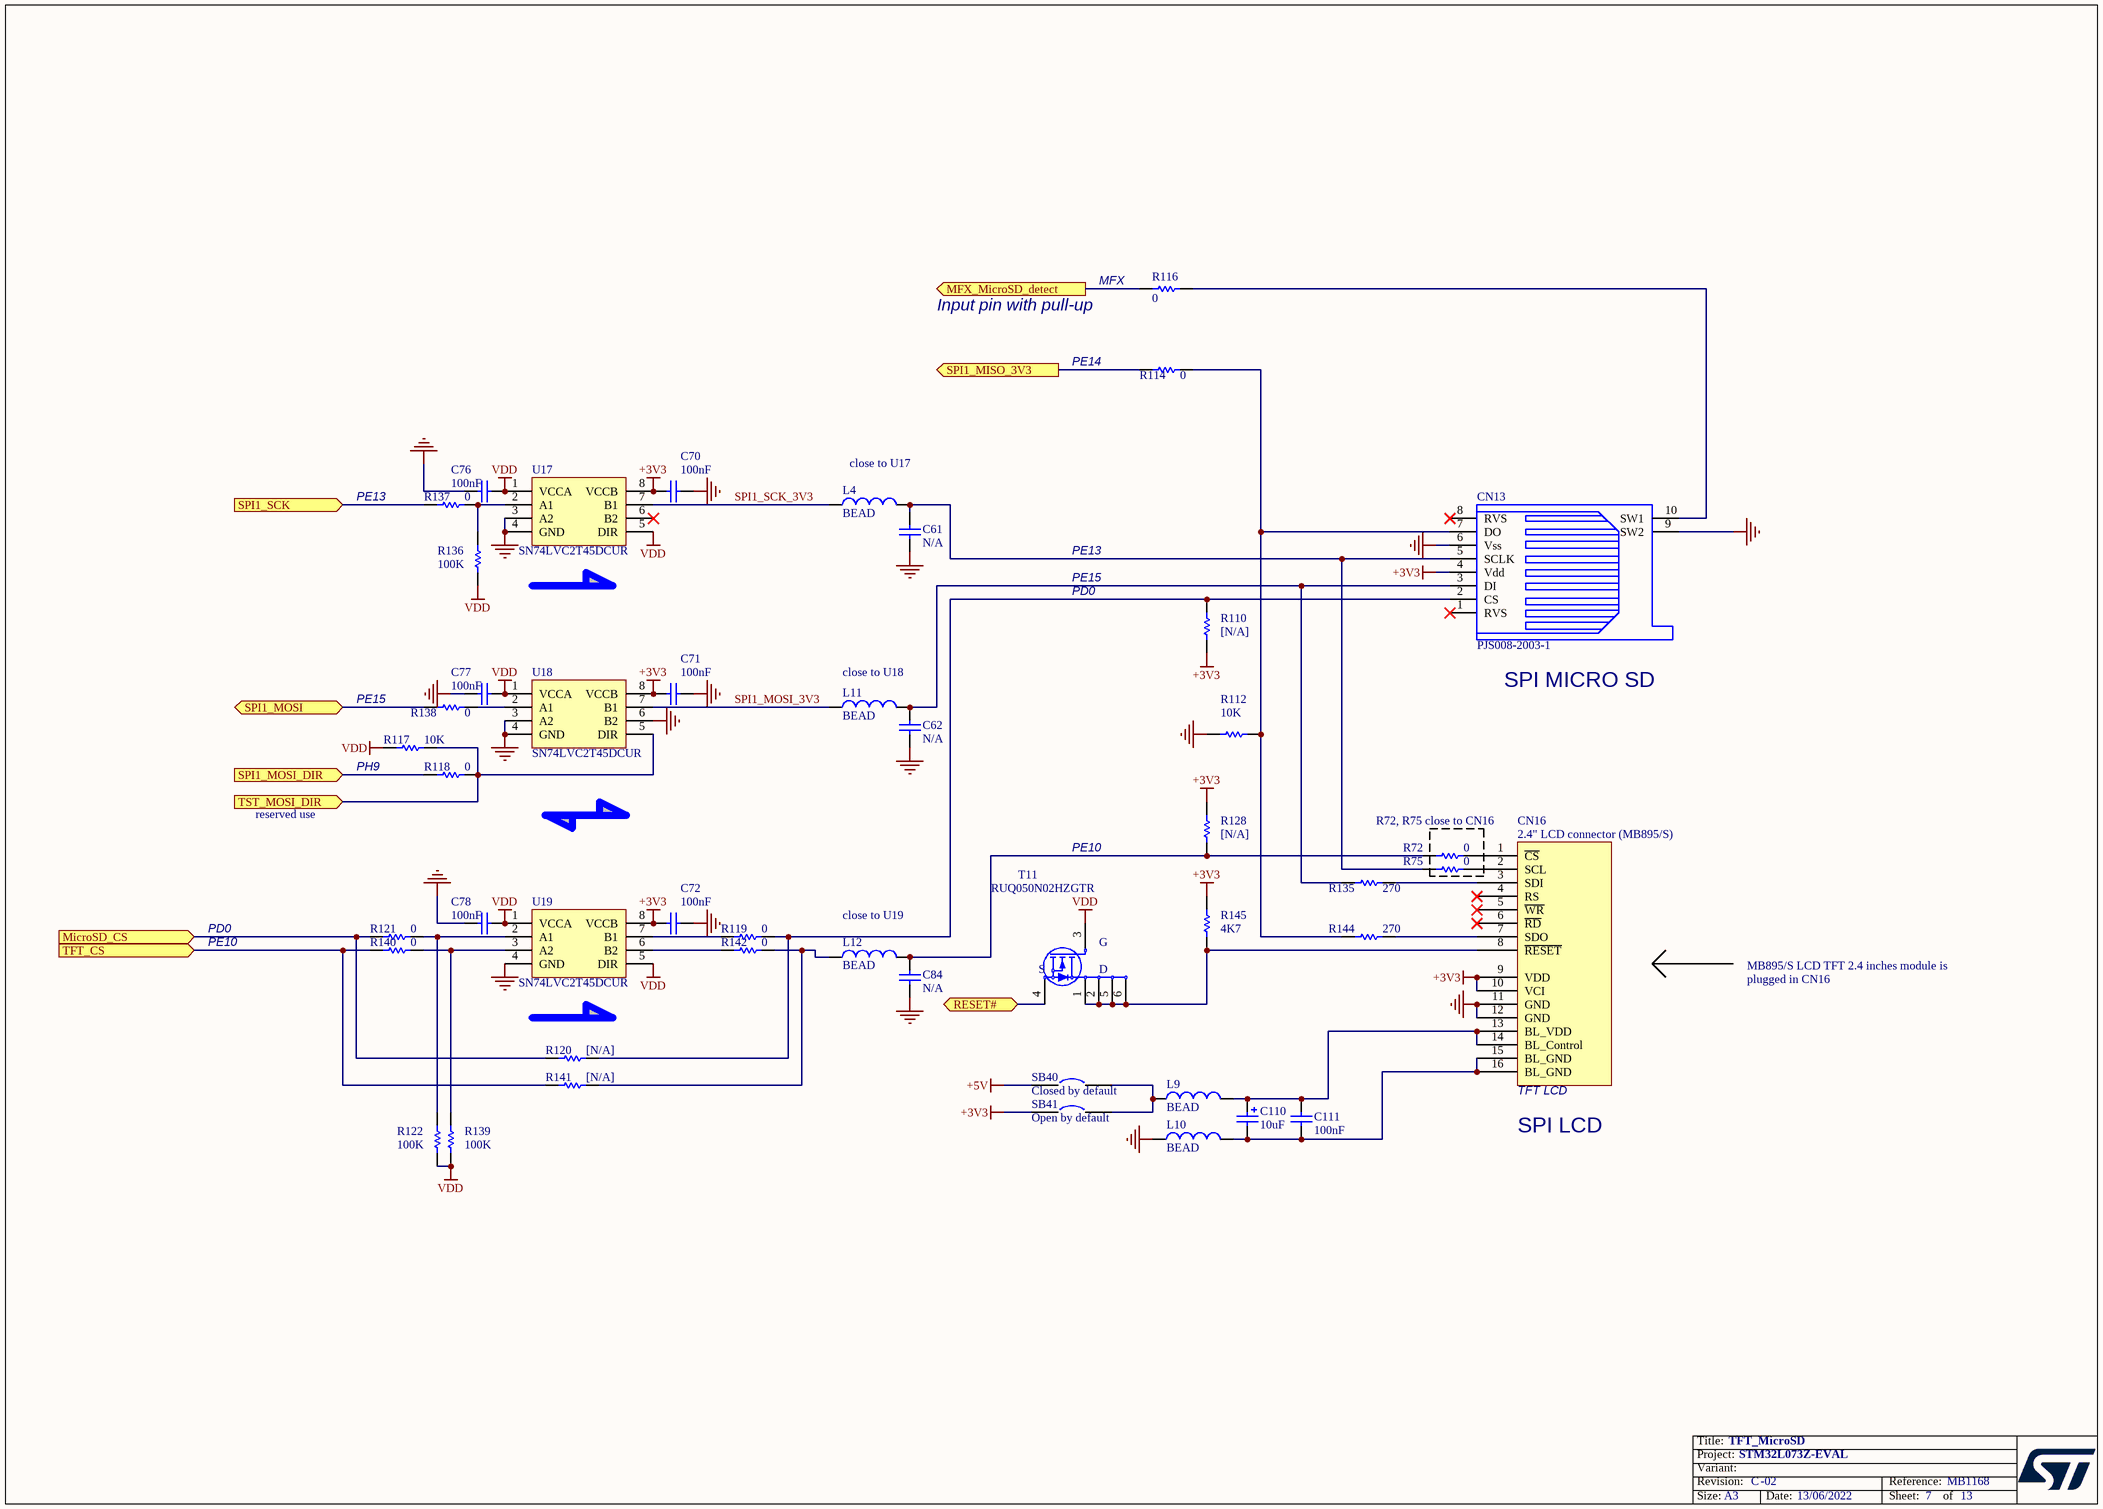
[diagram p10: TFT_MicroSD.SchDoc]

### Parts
C61  N/A  [0603C]
C62  N/A  [0603C]
C70  100nF  [0402C]
C71  100nF  [0402C]
C72  100nF  [0402C]
C76  100nF  [0402C]
C77  100nF  [0402C]
C78  100nF  [0402C]
C84  N/A  [0603C]
C110  10uF  [TAN-A]
C111  100nF  [0402C]
CN13  PJS008-2003-1  [MSD_PJS008_]
CN16  2.4" LCD connector (MB895/S)  [MB895CS]
L4  BEAD  [0603L]
L9  BEAD  [0603L]
L10  BEAD  [0603L]
L11  BEAD  [0603L]
L12  BEAD  [0603L]
R72  0  [0603R]
R75  0  [0603R]
R110  [N/A]  [0603R]
R112  10K  [0402R]
R114  0  [0603R]
R116  0  [0603R]
R117  10K  [0402R]
R118  0  [0603R]
R119  0  [0603R]
R120  [N/A]  [0603R]
R121  0  [0603R]
R122  100K  [0603R]
R128  [N/A]  [0603R]
R135  270  [0603R]
R136  100K  [0603R]
R137  0  [0603R]
R138  0  [0603R]
R139  100K  [0603R]
R140  0  [0603R]
R141  [N/A]  [0603R]
R142  0  [0603R]
R144  270  [0603R]
R145  4K7  [0402R]
SB40  Closed by default  [SB_0603]
SB41  Open by default  [SB_0603]
T11  RUQ050N02HZGTR  [SOT23-6L]
U17  SN74LVC2T45DCUR  [USOP8_0R5_2X3R1]
U18  SN74LVC2T45DCUR  [USOP8_0R5_2X3R1]
U19  SN74LVC2T45DCUR  [USOP8_0R5_2X3R1]

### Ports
MFX_MicroSD_detect (out), MicroSD_CS (in), RESET# (bidir), SPI1_MISO_3V3 (out), SPI1_MOSI (bidir), SPI1_MOSI_DIR (in), SPI1_SCK (in), TFT_CS (in), TST_MOSI_DIR (in)

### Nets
+3V3: C70.2 C71.2 C72.2 CN13.4(Vdd) CN16.9(VDD) CN16.10(VCI) R110.2 R128.2 R145.2 SB41.1 U17.8(VCCB) U18.8(VCCB) U19.8(VCCB)
+5V: SB40.1
GND: C61.1 C62.1 C70.1 C71.1 C72.1 C76.1 C77.1 C78.1 C84.1 CN13.6(Vss) CN13.9(SW2) CN16.11(GND) CN16.12(GND) L10.1 R112.1 U17.3(A2) U17.4(GND) U18.3(A2) U18.4(GND) U18.6(B2) U19.4(GND)
VDD: C76.2 C77.2 C78.2 R117.2 R122.2 R136.2 R139.2 T11.3(G) U17.1(VCCA) U17.5(DIR) U18.1(VCCA) U19.1(VCCA) U19.5(DIR)
PD0: R120.1 R121.2 ; port MicroSD_CS
PE10: R140.1 R141.1 ; port TFT_CS
PE13: R137.2 ; port SPI1_SCK
PE14: R114.2 ; port SPI1_MISO_3V3
PE15: R138.2 ; port SPI1_MOSI
PH9: R118.2 ; port SPI1_MOSI_DIR
RESET#: T11.4(S) ; port RESET#
SPI1_MOSI_3V3: L11.1 U18.7(B1)
SPI1_SCK_3V3: L4.1 U17.7(B1)
NetC61_2: C61.2 CN13.5(SCLK) L4.2 R75.1
NetC62_2: C62.2 CN13.3(DI) L11.2 R135.2
NetC84_2: C84.2 L12.2 R72.1 R128.1
NetC110_1: C110.1 C111.1 CN16.13(BL_VDD) CN16.14(BL_Control) L9.2
NetC110_2: C110.2 C111.2 CN16.15(BL_GND) CN16.16(BL_GND) L10.2
NetCN13_2: CN13.2(CS) R110.1 R119.1 R120.2
NetCN13_7: CN13.7(DO) R112.2 R114.1 R144.1
NetCN13_10: CN13.10(SW1) R116.2
NetCN16_1: CN16.1(~{CS}) R72.2
NetCN16_2: CN16.2(SCL) R75.2
NetCN16_3: CN16.3(SDI) R135.1
NetCN16_7: CN16.7(SDO) R144.2
NetCN16_8: CN16.8(~{RESET}) R145.1 T11.1(S) T11.2(S) T11.5(D) T11.6(D)
NetL9_1: L9.1 SB40.2 SB41.2
NetL12_1: L12.1 R141.2 R142.1
NetR101_1: R117.1 R118.1 U18.5(DIR) ; port TST_MOSI_DIR
NetR116_1: R116.1 ; port MFX_MicroSD_detect
NetR119_2: R119.2 U19.7(B1)
NetR121_1: R121.1 R122.1 U19.2(A1)
NetR136_1: R136.1 R137.1 U17.2(A1)
NetR138_1: R138.1 U18.2(A1)
NetR139_1: R139.1 R140.2 U19.3(A2)
NetR142_2: R142.2 U19.6(B2)

Not connected (* = marked no-connect by the designer): CN13 1(RVS)* 8(RVS)*; CN16 4(RS)* 5(~{WR})* 6(~{RD})*; U17 6(B2)*

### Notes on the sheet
- (near R116) Input pin with pull-up
- (near R116) MFX
- PE14
- PE13
- close to U17
- PE15
- PD0
- close to U18
- SPI MICRO SD
- (near R117) PH9
- reserved use
- PE10
- R72, R75 close to CN16
- close to U19
- MB895/S LCD TFT 2.4 inches module is plugged in CN16
- (near CN16) TFT LCD
- (near CN16) SPI LCD

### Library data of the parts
C61 C62 C84 = CAP: Capacitor; Value: 100nF; Ordered by: Subcon; Fitted: NO
C70-C72 C76-C78 = CAP: as C117 on sheet Peripherals
C110 = Cap Pol1: as C79 on sheet Power
C111 = Cap: as C21 on sheet Power
CN13 = SMS016AFA5E: Manuf_1: Yamaichi; Ordered by: Subcon; Silkscreen: uSD; Assembly: with uSD card
CN16 = ColorLCD_module: Manuf_1: lwconn; Manuf_Part_1: 216208S1311; Ordered by: Subcon; Assembly: with MB895/S
L4 L11 L12 = Inductor: Bead,600R,350mA,0603; Manuf_1: Wurth Elektronik; Manuf_Part_1: 742861160; Manuf_Part_2: 742863160; Value: 100uH; Ordered by: Subcon
L9 L10 = Inductor: as L1 on sheet Power
R72 R75 R112 R114 R116-R118 R122 R135 R136 R139 R140 R144 R145 = Res1: Resistor; Value: 1K; Ordered by: Subcon
R110 R120 R128 R141 = Res1: as R3 on sheet Peripherals
R119 R121 R137 R138 R142 = res1: Resistor; Value: 1K; Ordered by: Subcon
SB40 = Circuit Breaker: as SB4 on sheet Peripherals
SB41 = Circuit Breaker: as SB38 on sheet Power
T11 = STT5N2VH5: STripFETV Power MOSFET, N-CHANNEL 20V - 0.025 - 5A - SOT23-6L; Manuf_1: ST; Ref St: 9153047; ECCN_US/EU: EAR99/NEC
U17-U19 = SN74LVC2T45DCUT: as U26 on sheet STLINK

## Sheet USART_LPUART.SchDoc: USART_LPUART
size A3; Project: STM32L073Z-EVAL; Date: Not used; ApprovedBy: Not used; CheckedBy: Not used; Author: Not used; CompanyName: STMicroelectronics; DrawnBy: Not used; Engineer: Not used; Organization: Not used; Address1: Not used; Address2: Not used; Address3: Not used; Address4: Not used; DocumentNumber: 7; Revision: Not used; SheetNumber: 8; SheetTotal: 13
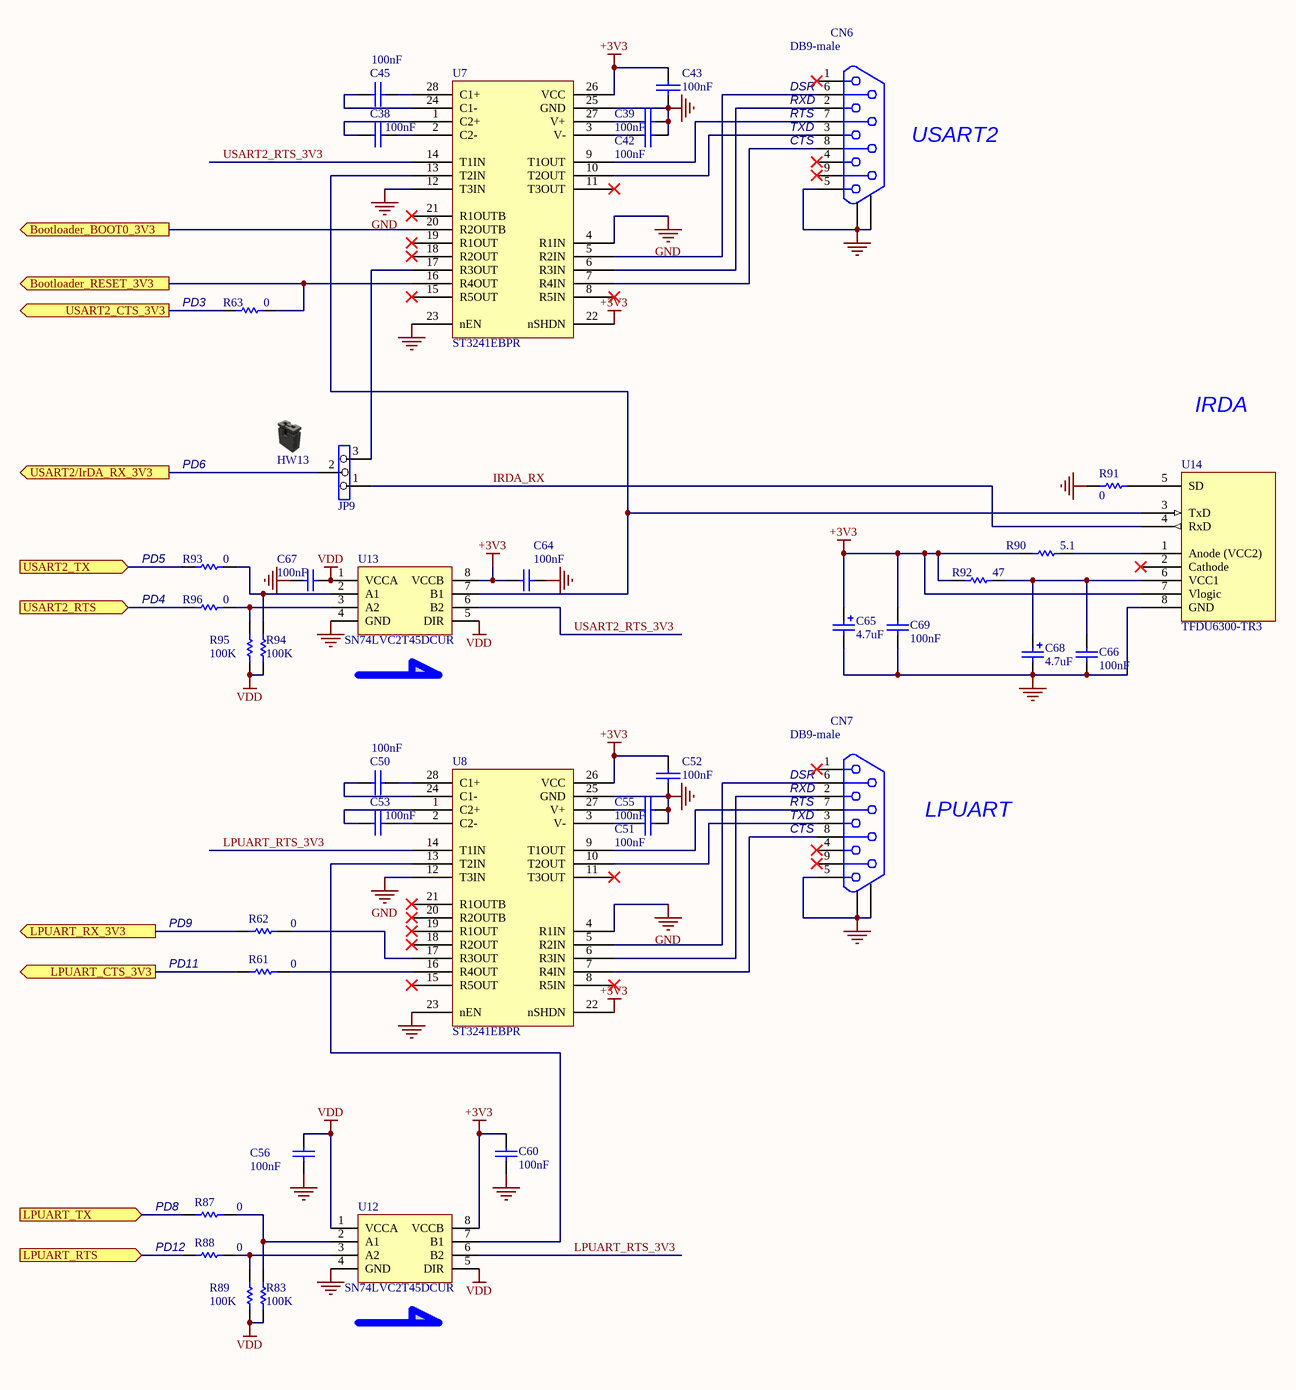
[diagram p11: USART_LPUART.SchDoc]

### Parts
C38  100nF  [0402C]
C39  100nF  [0402C]
C42  100nF  [0402C]
C43  100nF  [0402C]
C45  100nF  [0402C]
C50  100nF  [0402C]
C51  100nF  [0402C]
C52  100nF  [0402C]
C53  100nF  [0402C]
C55  100nF  [0402C]
C56  100nF  [0402C]
C60  100nF  [0402C]
C64  100nF  [0402C]
C65  4.7uF  [TAN-A]
C66  100nF  [0402C]
C67  100nF  [0402C]
C68  4.7uF  [TAN-A]
C69  100nF  [0402C]
CN6  DB9-male  [DB9/M]
CN7  DB9-male  [DB9/M]
HW13  Shunt Black 2.54mm  (value not drawn)  (mechanical)
JP9  (no value)  [SIP3]
R61  0  [0603R]
R62  0  [0603R]
R63  0  [0603R]
R83  100K  [0402R]
R87  0  [0603R]
R88  0  [0603R]
R89  100K  [0402R]
R90  5.1  [0402R]
R91  0  [0603R]
R92  47  [0402R]
R93  0  [0603R]
R94  100K  [0402R]
R95  100K  [0402R]
R96  0  [0603R]
U7  ST3241EBPR  [SSOP28_0R65_10R2X7R8]
U8  ST3241EBPR  [SSOP28_0R65_10R2X7R8]
U12  SN74LVC2T45DCUR  [USOP8_0R5_2X3R1]
U13  SN74LVC2T45DCUR  [USOP8_0R5_2X3R1]
U14  TFDU6300-TR3  [IR_VISHAY3]

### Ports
Bootloader_BOOT0_3V3 (out), Bootloader_RESET_3V3 (out), LPUART_CTS_3V3 (out), LPUART_RTS (in), LPUART_RX_3V3 (out), LPUART_TX (in), USART2/IrDA_RX_3V3 (out), USART2_CTS_3V3 (out), USART2_RTS (in), USART2_TX (in)

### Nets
+3V3: C43.2 C52.2 C60.2 C64.2 C65.1 C69.2 R90.1 R92.1 U7.22(nSHDN) U7.26(VCC) U8.22(nSHDN) U8.26(VCC) U12.8(VCCB) U13.8(VCCB) U14.7(Vlogic)
GND: C39.2 C42.2 C43.1 C51.2 C52.1 C55.2 C56.1 C60.1 C64.1 C65.2 C66.1 C67.1 C68.2 C69.1 CN6.5 CN6.10 CN6.11 CN7.5 CN7.10 CN7.11 R91.2 U7.4(R1IN) U7.12(T3IN) U7.23(nEN) U7.25(GND) U8.4(R1IN) U8.12(T3IN) U8.23(nEN) U8.25(GND) U12.4(GND) U13.4(GND) U14.8(GND)
VDD: C56.2 C67.2 R83.2 R89.2 R94.2 R95.2 U12.1(VCCA) U12.5(DIR) U13.1(VCCA) U13.5(DIR)
IRDA_RX: JP9.1 U14.4(RxD)
LPUART_RTS_3V3: U8.14(T1IN) U12.6(B2)
PD3: R63.2 ; port USART2_CTS_3V3
PD4: R96.2 ; port USART2_RTS
PD5: R93.2 ; port USART2_TX
USART2_RTS_3V3: U7.14(T1IN) U13.6(B2)
NetC38_1: C38.1 U7.1(C2+)
NetC38_2: C38.2 U7.2(C2-)
NetC39_1: C39.1 U7.27(V+)
NetC42_1: C42.1 U7.3(V-)
NetC45_1: C45.1 U7.24(C1-)
NetC45_2: C45.2 U7.28(C1+)
NetC50_1: C50.1 U8.24(C1-)
NetC50_2: C50.2 U8.28(C1+)
NetC51_1: C51.1 U8.3(V-)
NetC53_1: C53.1 U8.1(C2+)
NetC53_2: C53.2 U8.2(C2-)
NetC55_1: C55.1 U8.27(V+)
NetC66_2: C66.2 C68.1 R92.2 U14.6(VCC1)
NetCN6_2: CN6.2 U7.6(R3IN)
NetCN6_3: CN6.3 U7.10(T2OUT)
NetCN6_6: CN6.6 U7.5(R2IN)
NetCN6_7: CN6.7 U7.9(T1OUT)
NetCN6_8: CN6.8 U7.7(R4IN)
NetCN7_2: CN7.2 U8.6(R3IN)
NetCN7_3: CN7.3 U8.10(T2OUT)
NetCN7_6: CN7.6 U8.5(R2IN)
NetCN7_7: CN7.7 U8.9(T1OUT)
NetCN7_8: CN7.8 U8.7(R4IN)
NetCN14_24: R87.1 ; port LPUART_TX
NetCN14_26: R62.1 ; port LPUART_RX_3V3
NetCN14_30: R61.1 ; port LPUART_CTS_3V3
NetCN14_32: R88.1 ; port LPUART_RTS
NetD2_2: R63.1 U7.16(R4OUT) ; port Bootloader_RESET_3V3
NetJP9_2: JP9.2 ; port USART2/IrDA_RX_3V3
NetJP9_3: JP9.3 U7.17(R3OUT)
NetR35_2: U7.20(R2OUTB) ; port Bootloader_BOOT0_3V3
NetR61_2: R61.2 U8.16(R4OUT)
NetR62_2: R62.2 U8.17(R3OUT)
NetR83_1: R83.1 R87.2 U12.2(A1)
NetR88_2: R88.2 R89.1 U12.3(A2)
NetR90_2: R90.2 U14.1(Anode_(VCC2))
NetR91_1: R91.1 U14.5(SD)
NetR93_1: R93.1 R94.1 U13.2(A1)
NetR95_1: R95.1 R96.1 U13.3(A2)
NetU7_13: U7.13(T2IN) U13.7(B1) U14.3(TxD)
NetU8_13: U8.13(T2IN) U12.7(B1)

Not connected (* = marked no-connect by the designer): CN6 1* 4* 9*; CN7 1* 4* 9*; U7 8(R5IN)* 11(T3OUT)* 15(R5OUT)* 18(R2OUT)* 19(R1OUT)* 21(R1OUTB)*; U8 8(R5IN)* 11(T3OUT)* 15(R5OUT)* 18(R2OUT)* 19(R1OUT)* 20(R2OUTB)* 21(R1OUTB)*; U14 2(Cathode)*

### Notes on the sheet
- (near CN6) RXD
- (near CN6) DSR
- (near CN6) RTS
- (near CN6) TXD
- (near CN6) CTS
- (near CN6) USART2
- (near R63) PD3
- IRDA
- PD6
- PD5
- PD4
- (near CN7) DSR
- (near CN7) RXD
- (near CN7) RTS
- (near CN7) TXD
- (near CN7) CTS
- LPUART
- PD11
- PD9
- (near R88) PD12
- (near R87) PD8

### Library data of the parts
C38 C39 C42 C43 C45 C50-C53 C55 = CAP: Capacitor; Ordered by: Subcon
C56 C60 C64 C66 C67 C69 = CAP: as C117 on sheet Peripherals
C65 C68 = Cap Pol1: as C79 on sheet Power
CN6 = DB9: Manuf_1: lwconn; Manuf_Part_1: 50209M30111; Ordered by: Subcon; Comments: DB9 USART; Silkscreen: USART2
CN7 = DB9: Manuf_1: lwconn; Manuf_Part_1: 50209M30111; Ordered by: Subcon; Comments: DB9 USART; Silkscreen: LPUART
JP9 = Jumper3: Ordered by: Subcon; Silkscreen: 1,2: IRDA / 2,3: USART; Assembly: 2-3 (USART)
R61-R63 R83 R87-R96 = Res1: Resistor; Value: 1K; Ordered by: Subcon
U7 U8 = ST3241: Ordered by: ST; ECCN_US/EU: EAR99/NEC; Ref St: 9176312
U12 U13 = SN74LVC2T45DCUT: as U26 on sheet STLINK
U14 = TFDU4300: Ordered by: Subcon; ECCN_US/EU: EAR99/NEC

## Sheet SWD_Touch_USB.SchDoc: SWD_Touch_USB.SchDoc
size A3; Project: STM32L073Z-EVAL; Date: Not used; ApprovedBy: Not used; CheckedBy: Not used; Author: Not used; CompanyName: STMicroelectronics; DrawnBy: Not used; Engineer: Not used; Organization: Not used; Address1: Not used; Address2: Not used; Address3: Not used; Address4: Not used; DocumentNumber: 11; Revision: Not used; SheetNumber: 12; SheetTotal: 13
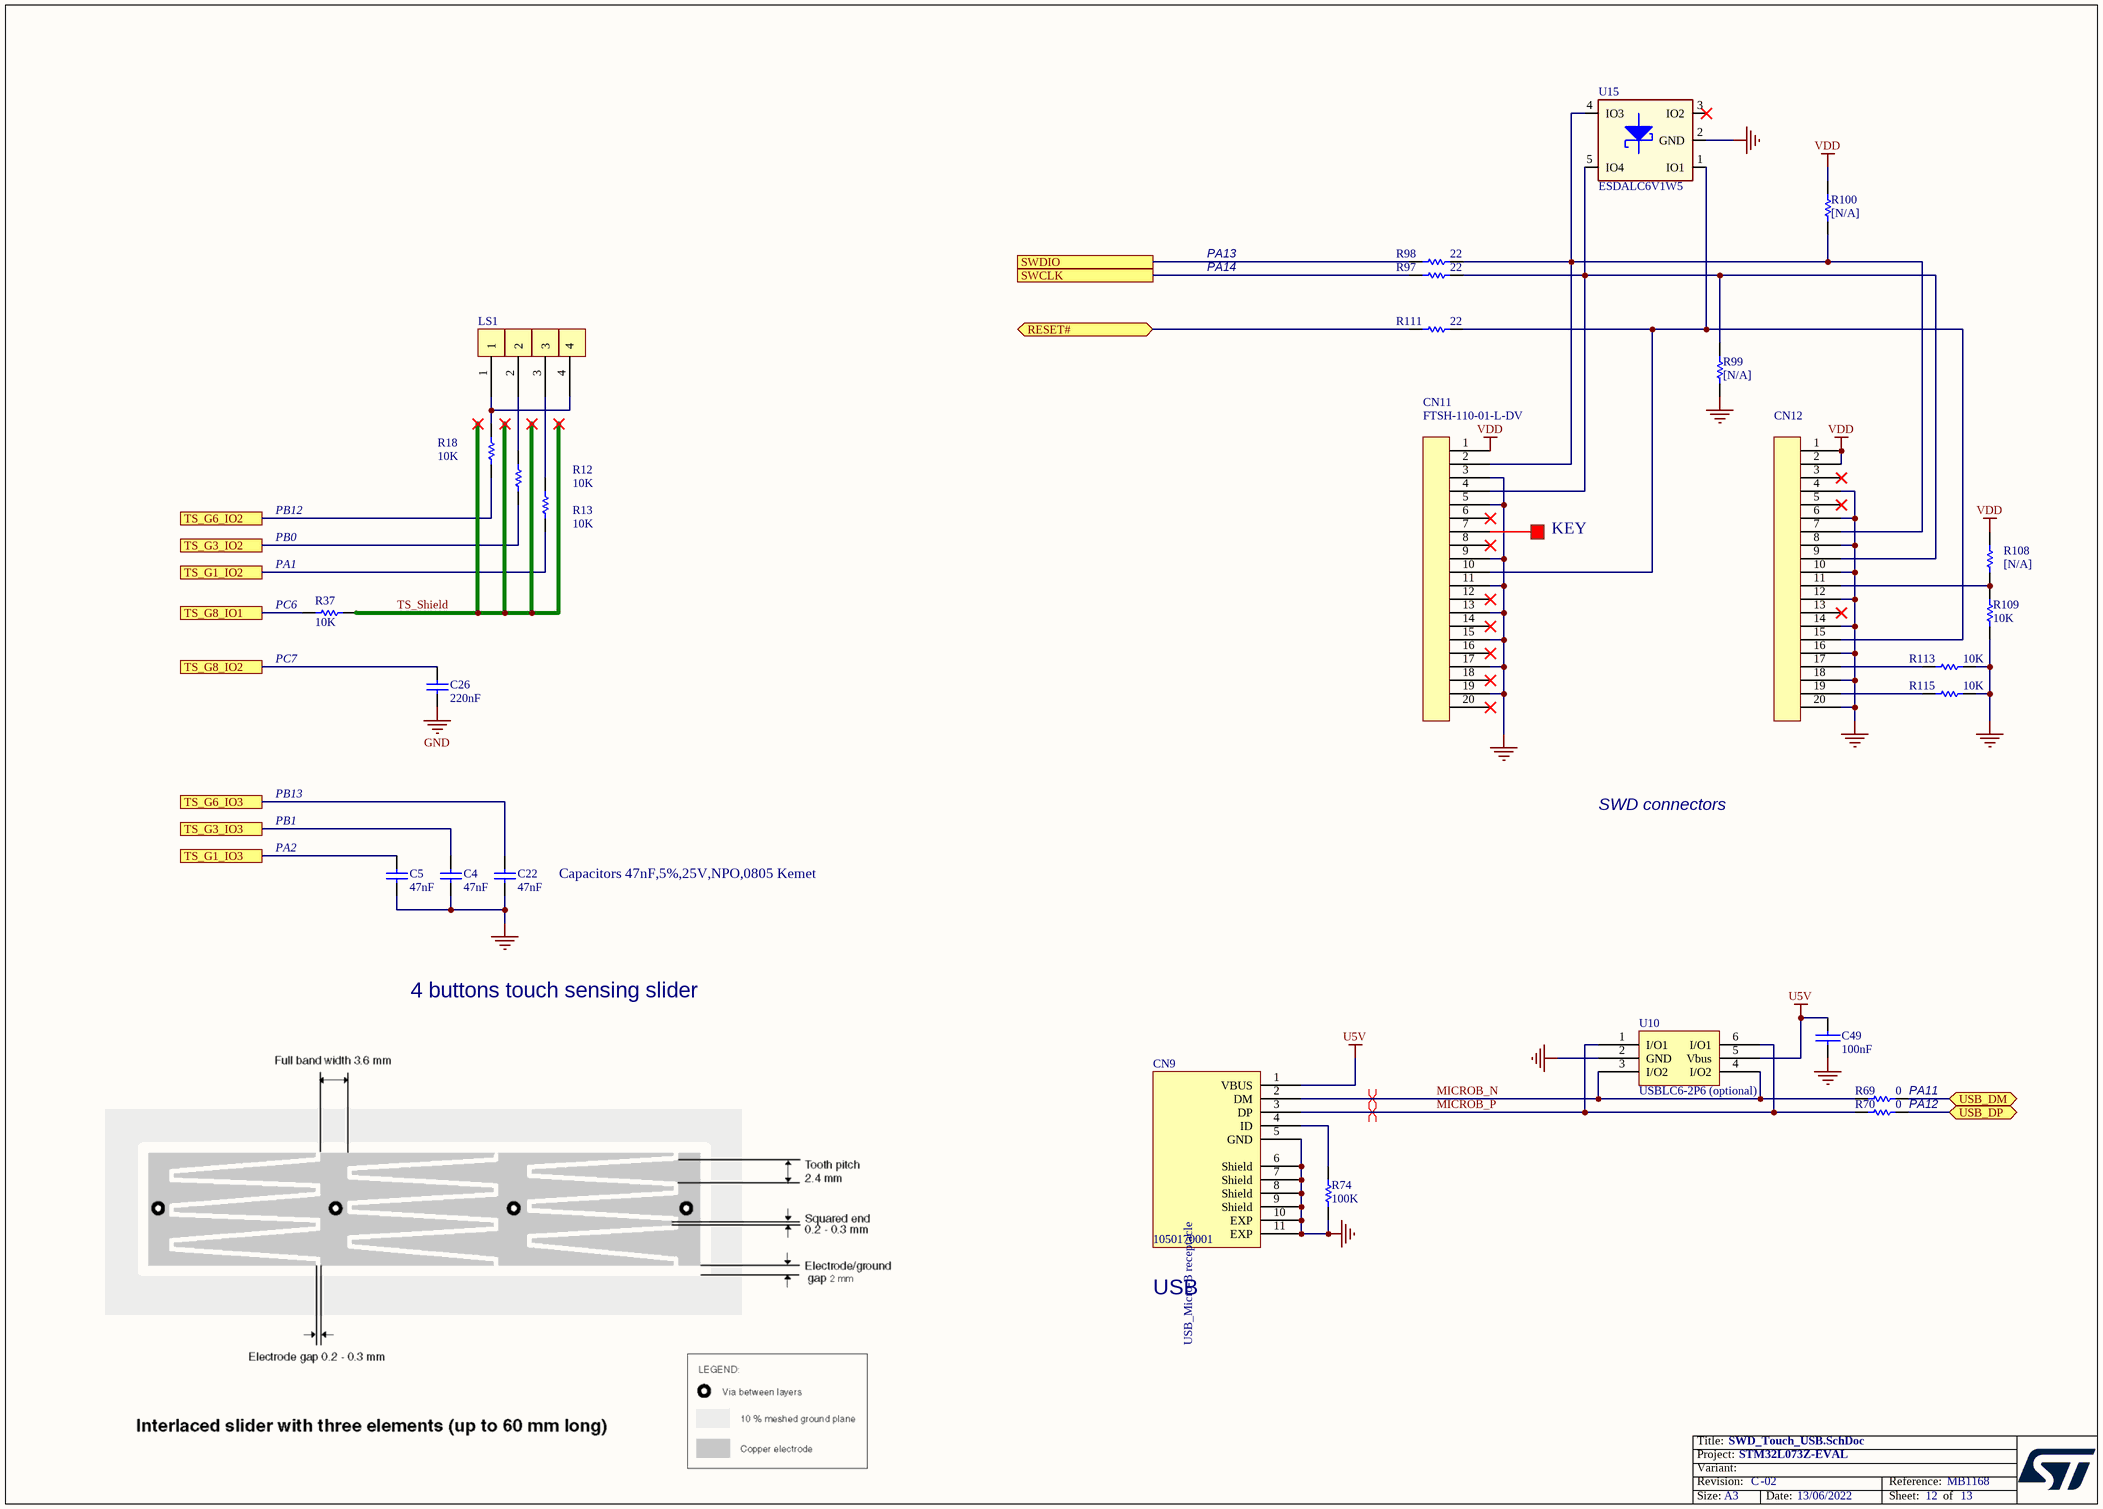
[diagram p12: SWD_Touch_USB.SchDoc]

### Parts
C4  47nF  [0805C]
C5  47nF  [0805C]
C22  47nF  [0805C]
C26  220nF  [0603C]
C49  100nF  [0402C]
CN9  1050170001  [MICRO_USB_B_105017]
CN11  FTSH-110-01-L-DV  [FTSH-110-01-L-DV]
CN12  JTAG  [IDC20S]  (value not drawn)
LS1  LS4  [LINEAR_SENSOR3_ELECTRODES]  (value not drawn)
R12  10K  [0603R]
R13  10K  [0603R]
R18  10K  [0603R]
R37  10K  [0603R]
R69  0  [0603R]
R70  0  [0603R]
R74  100K  [0603R]
R97  22  [0402R]
R98  22  [0402R]
R99  [N/A]  [0603R]
R100  [N/A]  [0603R]
R108  [N/A]  [0603R]
R109  10K  [0402R]
R111  22  [0402R]
R113  10K  [0402R]
R115  10K  [0402R]
U10  USBLC6-2P6 (optional)  [SOT-563]
U15  ESDALC6V1W5  [SOT-353]

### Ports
RESET# (bidir), SWCLK, SWDIO, TS_G1_IO2, TS_G1_IO3, TS_G3_IO2, TS_G3_IO3, TS_G6_IO2, TS_G6_IO3, TS_G8_IO1, TS_G8_IO2, USB_DM (bidir), USB_DP (bidir)

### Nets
GND: C4.1 C5.1 C22.1 C26.1 C49.2 CN9.5(GND) CN9.6(Shield) CN9.7(Shield) CN9.8(Shield) CN9.9(Shield) CN9.10(EXP) CN9.11(EXP) CN11.3 CN11.5 CN11.9 CN11.11 CN11.13 CN11.15 CN11.17 CN11.19 CN12.4 CN12.6 CN12.8 CN12.10 CN12.12 CN12.14 CN12.16 CN12.18 CN12.20 R74.1 R99.1 R109.1 R113.1 R115.1 U10.2(GND) U15.2(GND)
U5V: C49.1 CN9.1(VBUS) U10.5(Vbus)
VDD: CN11.1 CN12.1 CN12.2 R100.2 R108.2
MICROB_N: CN9.2(DM) R69.2 U10.3(I/O2) U10.4(I/O2)
MICROB_P: CN9.3(DP) R70.2 U10.1(I/O1) U10.6(I/O1)
PA11: R69.1 ; port USB_DM
PA12: R70.1 ; port USB_DP
RESET#: R111.2 ; port RESET#
T_JTCK: R97.2 ; port SWCLK
T_JTMS: R98.2 ; port SWDIO
TS_Shield: R37.1
NetC4_2: C4.2 ; port TS_G3_IO3
NetC5_2: C5.2 ; port TS_G1_IO3
NetC22_2: C22.2 ; port TS_G6_IO3
NetC26_2: C26.2 ; port TS_G8_IO2
NetCN9_4: CN9.4(ID) R74.2
NetCN11_2: CN11.2 CN12.7 R98.1 R100.1 U15.4(IO3)
NetCN11_4: CN11.4 CN12.9 R97.1 R99.2 U15.5(IO4)
NetCN11_10: CN11.10 CN12.15 R111.1 U15.1(IO1)
NetCN12_11: CN12.11 R108.1 R109.2
NetCN12_17: CN12.17 R113.2
NetCN12_19: CN12.19 R115.2
NetLS1_1: LS1.1 LS1.4 R18.2
NetLS1_2: LS1.2 R12.2
NetLS1_3: LS1.3 R13.2
NetR12_1: R12.1 ; port TS_G3_IO2
NetR13_1: R13.1 ; port TS_G1_IO2
NetR18_1: R18.1 ; port TS_G6_IO2
NetR37_2: R37.2 ; port TS_G8_IO1

Not connected (* = marked no-connect by the designer): CN11 6* 7 8* 12* 14* 16* 18* 20*; CN12 3* 5* 13*; U15 3(IO2)*

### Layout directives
differential pair: MICROB_N, MICROB_P

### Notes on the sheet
- PA13
- PA14
- PB12
- PB0
- (near R37) PA1
- KEY
- (near R37) PC6
- (near R37) PC7
- PB13
- PB1
- PA2
- SWD connectors
- Capacitors 47nF,5%,25V,NPO,0805 Kemet
- 4 buttons touch sensing slider
- PA12
- PA11
- USB

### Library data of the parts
C4 C5 C22 = Cap_47nF_NPO_5%: Capacitor 47nF,5%,25V,NPO,0805 Kemet; Order: C0805C473J3GACTU; Ordered by: Subcon
C26 = Cap: as C21 on sheet Power
C49 = CAP: Capacitor; Ordered by: Subcon
CN9 = 1050170001: Manuf_1: MOLEX; Silkscreen: USB; Ordered by: Subcon
CN11 = 20PIN1: Manuf_1: towneS; Manuf_Part_1: P127B-2*10MGF-079-1E7; Ordered by: Subcon; Comments: Trace connector; Assembly: with pin7 removed; Silkscreen: Trace
CN12 = 20PIN1: Manuf_1: lwconn; Manuf_Part_1: 302520S01B0; Ordered by: Subcon; Comments: JTAG connector
LS1 = LS4: Ordered by: Subcon
R12 R13 R18 R37 = res1: Resistor; Value: 1K; Ordered by: Subcon
R69 R70 R74 R97 R98 R109 R111 R113 R115 = Res1: Resistor; Value: 1K; Ordered by: Subcon
R99 R100 R108 = Res1: as R3 on sheet Peripherals
U10 = USBLC6-2: Ordered by: ST; ECCN_US/EU: EAR99/NEC; Ref St: 9151057
U15 = ESDALC6V1W5: Dual Transil array for ESD protection; Manuf_1: ST; Ref St: 9151112; ECCN_US/EU: EAR99/NEC

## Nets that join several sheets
+3V3: IDD_measurement (R170.1), LCD_Glass_Ext_connector (R19.1), Peripherals (5 pins), Power (7 pins), TFT_MicroSD (13 pins), USART_LPUART (15 pins)
+5V: IDD_measurement (R151.1), Peripherals (C117.2 LD7.1 U28.8), Power (12 pins), STLINK (D7.1), TFT_MicroSD (SB40.1)
AGND: ADC16b_Pressure (12 pins), Power (7 pins)
D5V: LCD_Glass_Ext_connector (CN4.24), Power (JP11.2), STLINK (D5.1)
E5V: Power (C96.1 JP11.8 L8.3), STLINK (D3.1)
GND: MCU (13 pins), Detection (10 pins), IDD_measurement (29 pins), LCD_Glass_Ext_connector (16 pins), Peripherals (16 pins), Power (57 pins), STLINK (34 pins), TFT_MicroSD (21 pins), USART_LPUART (32 pins), SWD_Touch_USB (36 pins)
U5V: Power (C44.1 JP11.6 U6.6), STLINK (D4.1), SWD_Touch_USB (C49.1 CN9.1 U10.5)
U5V_STLINK: Power (L5.2 SB38.1), STLINK (C54.2 U29.6 U29.7)
VDD: MCU (R53.2 R56.2 R213.2 SW1.1), IDD_measurement (23 pins), LCD_Glass_Ext_connector (CN5.26), Peripherals (10 pins), Power (5 pins), STLINK (5 pins), TFT_MicroSD (13 pins), USART_LPUART (10 pins), SWD_Touch_USB (5 pins)
VDD_ANA: ADC16b_Pressure (10 pins), Power (R43.2 R44.2)
VDD_MCU: MCU (C28.2 R47.1), IDD_measurement (JP10.2 R180.2), Power (11 pins)
VLCD: LCD_Glass_Ext_connector (CN5.17), Power (R50.1 U5.6)
BOOT0: MCU (JP3.1 R36.1 U5.94), LCD_Glass_Ext_connector (CN5.21)
LCDCOM0: MCU (U5.67), LCD_Glass_Ext_connector (CN10.3)
LCDCOM1: MCU (U5.68), LCD_Glass_Ext_connector (CN10.1)
LCDCOM2: MCU (U5.69), LCD_Glass_Ext_connector (CN10.5)
LCDCOM3: MCU (U5.96), LCD_Glass_Ext_connector (CN10.7)
LCDCOM4: MCU (U5.78), LCD_Glass_Ext_connector (CN14.7)
LCDCOM5: MCU (U5.79), LCD_Glass_Ext_connector (CN14.5)
LCDCOM6: MCU (U5.80), LCD_Glass_Ext_connector (CN14.3)
LCDCOM7: MCU (U5.83), LCD_Glass_Ext_connector (CN14.1)
LCDSEG0: MCU (SB12.1), LCD_Glass_Ext_connector (CN14.47)
LCDSEG1: MCU (SB9.1), LCD_Glass_Ext_connector (CN10.35)
LCDSEG2: MCU (U5.26), LCD_Glass_Ext_connector (CN10.33)
LCDSEG3: MCU (U5.31), LCD_Glass_Ext_connector (CN10.41)
LCDSEG4: MCU (JP1.1 JP14.2 SB28.2), LCD_Glass_Ext_connector (CN10.39)
LCDSEG5: MCU (5 pins), LCD_Glass_Ext_connector (CN10.37)
LCDSEG6: MCU (SB13.2), LCD_Glass_Ext_connector (CN10.47)
LCDSEG7: MCU (SB35.2), LCD_Glass_Ext_connector (CN10.45)
LCDSEG8: MCU (JP15.1 JP16.2 SB34.2), LCD_Glass_Ext_connector (CN10.43)
LCDSEG9: MCU (U5.91), LCD_Glass_Ext_connector (CN10.13)
LCDSEG10: MCU (U5.47), LCD_Glass_Ext_connector (CN10.11)
LCDSEG11: MCU (U5.48), LCD_Glass_Ext_connector (CN10.9)
LCDSEG12: MCU (SB5.2), LCD_Glass_Ext_connector (CN10.19)
LCDSEG13: MCU (SB16.2), LCD_Glass_Ext_connector (CN10.17)
LCDSEG14: MCU (U5.53), LCD_Glass_Ext_connector (CN10.15)
LCDSEG15: MCU (U5.54), LCD_Glass_Ext_connector (CN10.25)
LCDSEG16: MCU (U5.95), LCD_Glass_Ext_connector (CN10.23)
LCDSEG17: MCU (U5.77), LCD_Glass_Ext_connector (CN10.21)
LCDSEG18: MCU (JP17.1 JP18.2 SB36.2), LCD_Glass_Ext_connector (CN10.31)
LCDSEG19: MCU (JP18.1 SB36.1 U5.16), LCD_Glass_Ext_connector (CN10.29)
LCDSEG20: MCU (U5.17), LCD_Glass_Ext_connector (CN10.27)
LCDSEG21: MCU (U5.18), LCD_Glass_Ext_connector (CN14.9)
LCDSEG22: MCU (U5.33), LCD_Glass_Ext_connector (CN14.11)
LCDSEG23: MCU (U5.34), LCD_Glass_Ext_connector (CN14.13)
LCDSEG24: MCU (SB18.1), LCD_Glass_Ext_connector (CN14.15)
LCDSEG25: MCU (SB22.1), LCD_Glass_Ext_connector (CN14.17)
LCDSEG26: MCU (U5.65), LCD_Glass_Ext_connector (CN14.19)
LCDSEG27: MCU (U5.66), LCD_Glass_Ext_connector (CN14.21)
LCDSEG28: MCU (U5.55), LCD_Glass_Ext_connector (CN14.23)
LCDSEG29: MCU (U5.56), LCD_Glass_Ext_connector (CN14.25)
LCDSEG30: MCU (U5.57), LCD_Glass_Ext_connector (CN14.27)
LCDSEG31: MCU (U5.58), LCD_Glass_Ext_connector (CN14.29)
LCDSEG32: MCU (U5.59), LCD_Glass_Ext_connector (CN14.31)
LCDSEG33: MCU (U5.60), LCD_Glass_Ext_connector (CN14.33)
LCDSEG34: MCU (U5.61), LCD_Glass_Ext_connector (CN14.35)
LCDSEG35: MCU (U5.62), LCD_Glass_Ext_connector (CN14.37)
LCDSEG36: MCU (U5.97), LCD_Glass_Ext_connector (CN14.39)
LCDSEG37: MCU (U5.98), LCD_Glass_Ext_connector (CN14.41)
LCDSEG38: MCU (U5.1), LCD_Glass_Ext_connector (CN14.43)
LCDSEG39: MCU (U5.2), LCD_Glass_Ext_connector (CN14.45)
NetB3_1: IDD_measurement (U25.20), Peripherals (B3.1)
NetB3_2: IDD_measurement (U25.18), Peripherals (B3.2)
NetB3_3: IDD_measurement (U25.19), Peripherals (B3.3)
NetB3_4: IDD_measurement (U25.39), Peripherals (B3.4)
NetB3_6: IDD_measurement (U25.40), Peripherals (B3.6)
NetC4_2: MCU (SB7.2), SWD_Touch_USB (C4.2)
NetC5_2: MCU (SB10.1), SWD_Touch_USB (C5.2)
NetC22_2: MCU (SB15.2), SWD_Touch_USB (C22.2)
NetC26_2: MCU (SB24.1), SWD_Touch_USB (C26.2)
NetC59_1: MCU (JP2.3), Detection (C59.1)
NetCN1_4: LCD_Glass_Ext_connector (CN14.44), Peripherals (CN1.4 R3.1)
NetCN10_14: LCD_Glass_Ext_connector (CN10.14), Peripherals (R4.2)
NetCN14_24: LCD_Glass_Ext_connector (CN14.24), USART_LPUART (R87.1)
NetCN14_26: LCD_Glass_Ext_connector (CN14.26), USART_LPUART (R62.1)
NetCN14_30: LCD_Glass_Ext_connector (CN14.30), USART_LPUART (R61.1)
NetCN14_32: LCD_Glass_Ext_connector (CN14.32), USART_LPUART (R88.1)
NetD2_2: MCU (D2.2), USART_LPUART (R63.1 U7.16)
NetJP1_3: MCU (JP1.3 JP17.3), Detection (TP18.1)
NetJP2_1: MCU (JP2.1), Peripherals (R29.2)
NetJP8_2: MCU (JP15.3), Detection (JP8.2)
NetR1_1: MCU (R52.2 R53.1), Peripherals (R1.1 R10.1)
NetR2_1: MCU (R55.2 R56.1), Peripherals (R2.1 R9.1)
NetR12_1: MCU (SB8.2), SWD_Touch_USB (R12.1)
NetR13_1: MCU (SB11.1), SWD_Touch_USB (R13.1)
NetR18_1: MCU (SB6.2), SWD_Touch_USB (R18.1)
NetR35_2: MCU (R35.2), USART_LPUART (U7.20)
NetR37_2: MCU (SB17.1), SWD_Touch_USB (R37.2)
NetR101_1: LCD_Glass_Ext_connector (R101.1), TFT_MicroSD (R117.1 R118.1 U18.5)
NetR116_1: IDD_measurement (U25.15), TFT_MicroSD (R116.1)
PA0: MCU (U5.23), ADC16b_Pressure (R38.2), LCD_Glass_Ext_connector (CN5.5)
PA4: MCU (JP2.2 U5.29), LCD_Glass_Ext_connector (CN5.6)
PA5: MCU (U5.30), LCD_Glass_Ext_connector (CN5.3), Peripherals (R8.2)
PA11: MCU (U5.70), LCD_Glass_Ext_connector (CN4.14), SWD_Touch_USB (R69.1)
PA12: MCU (U5.71), LCD_Glass_Ext_connector (CN4.16), SWD_Touch_USB (R70.1)
PA13: MCU (R45.2 U5.72), LCD_Glass_Ext_connector (CN4.15)
PA14: MCU (R51.2 U5.76), LCD_Glass_Ext_connector (CN4.18)
PB2: MCU (R27.1 U5.37), LCD_Glass_Ext_connector (CN5.4)
PB6: MCU (R55.1 U5.92), LCD_Glass_Ext_connector (CN5.23)
PB7: MCU (R52.1 U5.93), LCD_Glass_Ext_connector (CN5.22)
PC13: MCU (U5.7), LCD_Glass_Ext_connector (R39.1), Peripherals (R214.2)
PC14: MCU (R49.2 U5.8), LCD_Glass_Ext_connector (SB27.1)
PC15: MCU (R48.2 U5.9), LCD_Glass_Ext_connector (SB26.1)
PD0: MCU (U5.81), LCD_Glass_Ext_connector (CN4.17), TFT_MicroSD (R120.1 R121.2)
PD1: MCU (U5.82), LCD_Glass_Ext_connector (CN4.20), Peripherals (R200.1)
PD3: MCU (U5.84), LCD_Glass_Ext_connector (CN4.19), USART_LPUART (R63.2)
PD4: MCU (U5.85), USART_LPUART (R96.2)
PD5: MCU (U5.86), LCD_Glass_Ext_connector (CN4.22), USART_LPUART (R93.2)
PD6: MCU (U5.87), LCD_Glass_Ext_connector (CN4.21)
PD7: MCU (U5.88), Detection (SB31.2 SB32.2), LCD_Glass_Ext_connector (CN4.23)
PE4: MCU (U5.3), LCD_Glass_Ext_connector (CN5.20), Peripherals (R202.1)
PE5: MCU (U5.4), LCD_Glass_Ext_connector (CN5.19), Peripherals (R201.1)
PE6: MCU (U5.5), IDD_measurement (R166.1), LCD_Glass_Ext_connector (CN5.18)
PE7: MCU (U5.38), LCD_Glass_Ext_connector (CN4.3), Peripherals (R199.1)
PE8: MCU (U5.39), LCD_Glass_Ext_connector (CN4.4), STLINK (R181.1)
PE9: MCU (U5.40), LCD_Glass_Ext_connector (CN4.5), STLINK (R187.2)
PE10: MCU (U5.41), LCD_Glass_Ext_connector (CN4.6), TFT_MicroSD (R140.1 R141.1)
PE11: MCU (R26.1 U5.42), LCD_Glass_Ext_connector (CN4.7)
PE12: MCU (R25.1 U5.43), LCD_Glass_Ext_connector (CN4.8)
PE13: MCU (U5.44), LCD_Glass_Ext_connector (CN4.9), TFT_MicroSD (R137.2)
PE14: MCU (U5.45), LCD_Glass_Ext_connector (CN4.10), TFT_MicroSD (R114.2)
PE15: MCU (U5.46), LCD_Glass_Ext_connector (CN4.13), TFT_MicroSD (R138.2)
PH0: MCU (C27.1 U5.12 X1.2), LCD_Glass_Ext_connector (SB25.1)
PH1: MCU (R42.1 U5.13), LCD_Glass_Ext_connector (SB23.1)
PH9: MCU (R46.2 U5.10), LCD_Glass_Ext_connector (CN5.10), TFT_MicroSD (R118.2)
PH10: MCU (R47.2 U5.11), IDD_measurement (R158.1), LCD_Glass_Ext_connector (CN5.9)
RESET#: MCU (6 pins), IDD_measurement (D8.2), LCD_Glass_Ext_connector (R41.1), STLINK (U24.18), TFT_MicroSD (T11.4), SWD_Touch_USB (R111.2)
T_JTCK: MCU (R51.1), STLINK (U24.15 U24.26), SWD_Touch_USB (R97.2)
T_JTMS: MCU (R45.1), STLINK (U24.27 U26.3), SWD_Touch_USB (R98.2)

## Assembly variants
L073VZT6: not fitted C2 C15 C16 C47 C57 C61 C62 C84 C89 C95 CN15 CN19 L3 R3 R30 R43 R46 R47 R99 R100 R101 R108 R110 R120 R128 R141 R147 R155 R176 R183 R213 SB6 SB7 SB8 SB10 SB11 SB15 SB17 SB23 SB24 SB25 SB26 SB27 SB28 SB32 SB33 SB34 SB36 SB38 SB41 T2 T4 T6 T8 T10 TP1 TP2 TP3 TP4 TP5 TP6 TP7 TP8 TP9 TP10 TP14 TP18 TP20 TP21 TP22 TP23 TP24 TP25 TP26 TP27 TP28 TP29 TP31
